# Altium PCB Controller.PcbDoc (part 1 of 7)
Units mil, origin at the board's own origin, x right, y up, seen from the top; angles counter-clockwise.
Board outline 9000 x 8000 mil, 6 copper layers (Top Layer, Layer 1, Layer 2, Layer 3, Layer 4, Bottom Layer), stack 61.699 mil thick; 761 components, 454 nets, 2369 pads, 1133 vias.
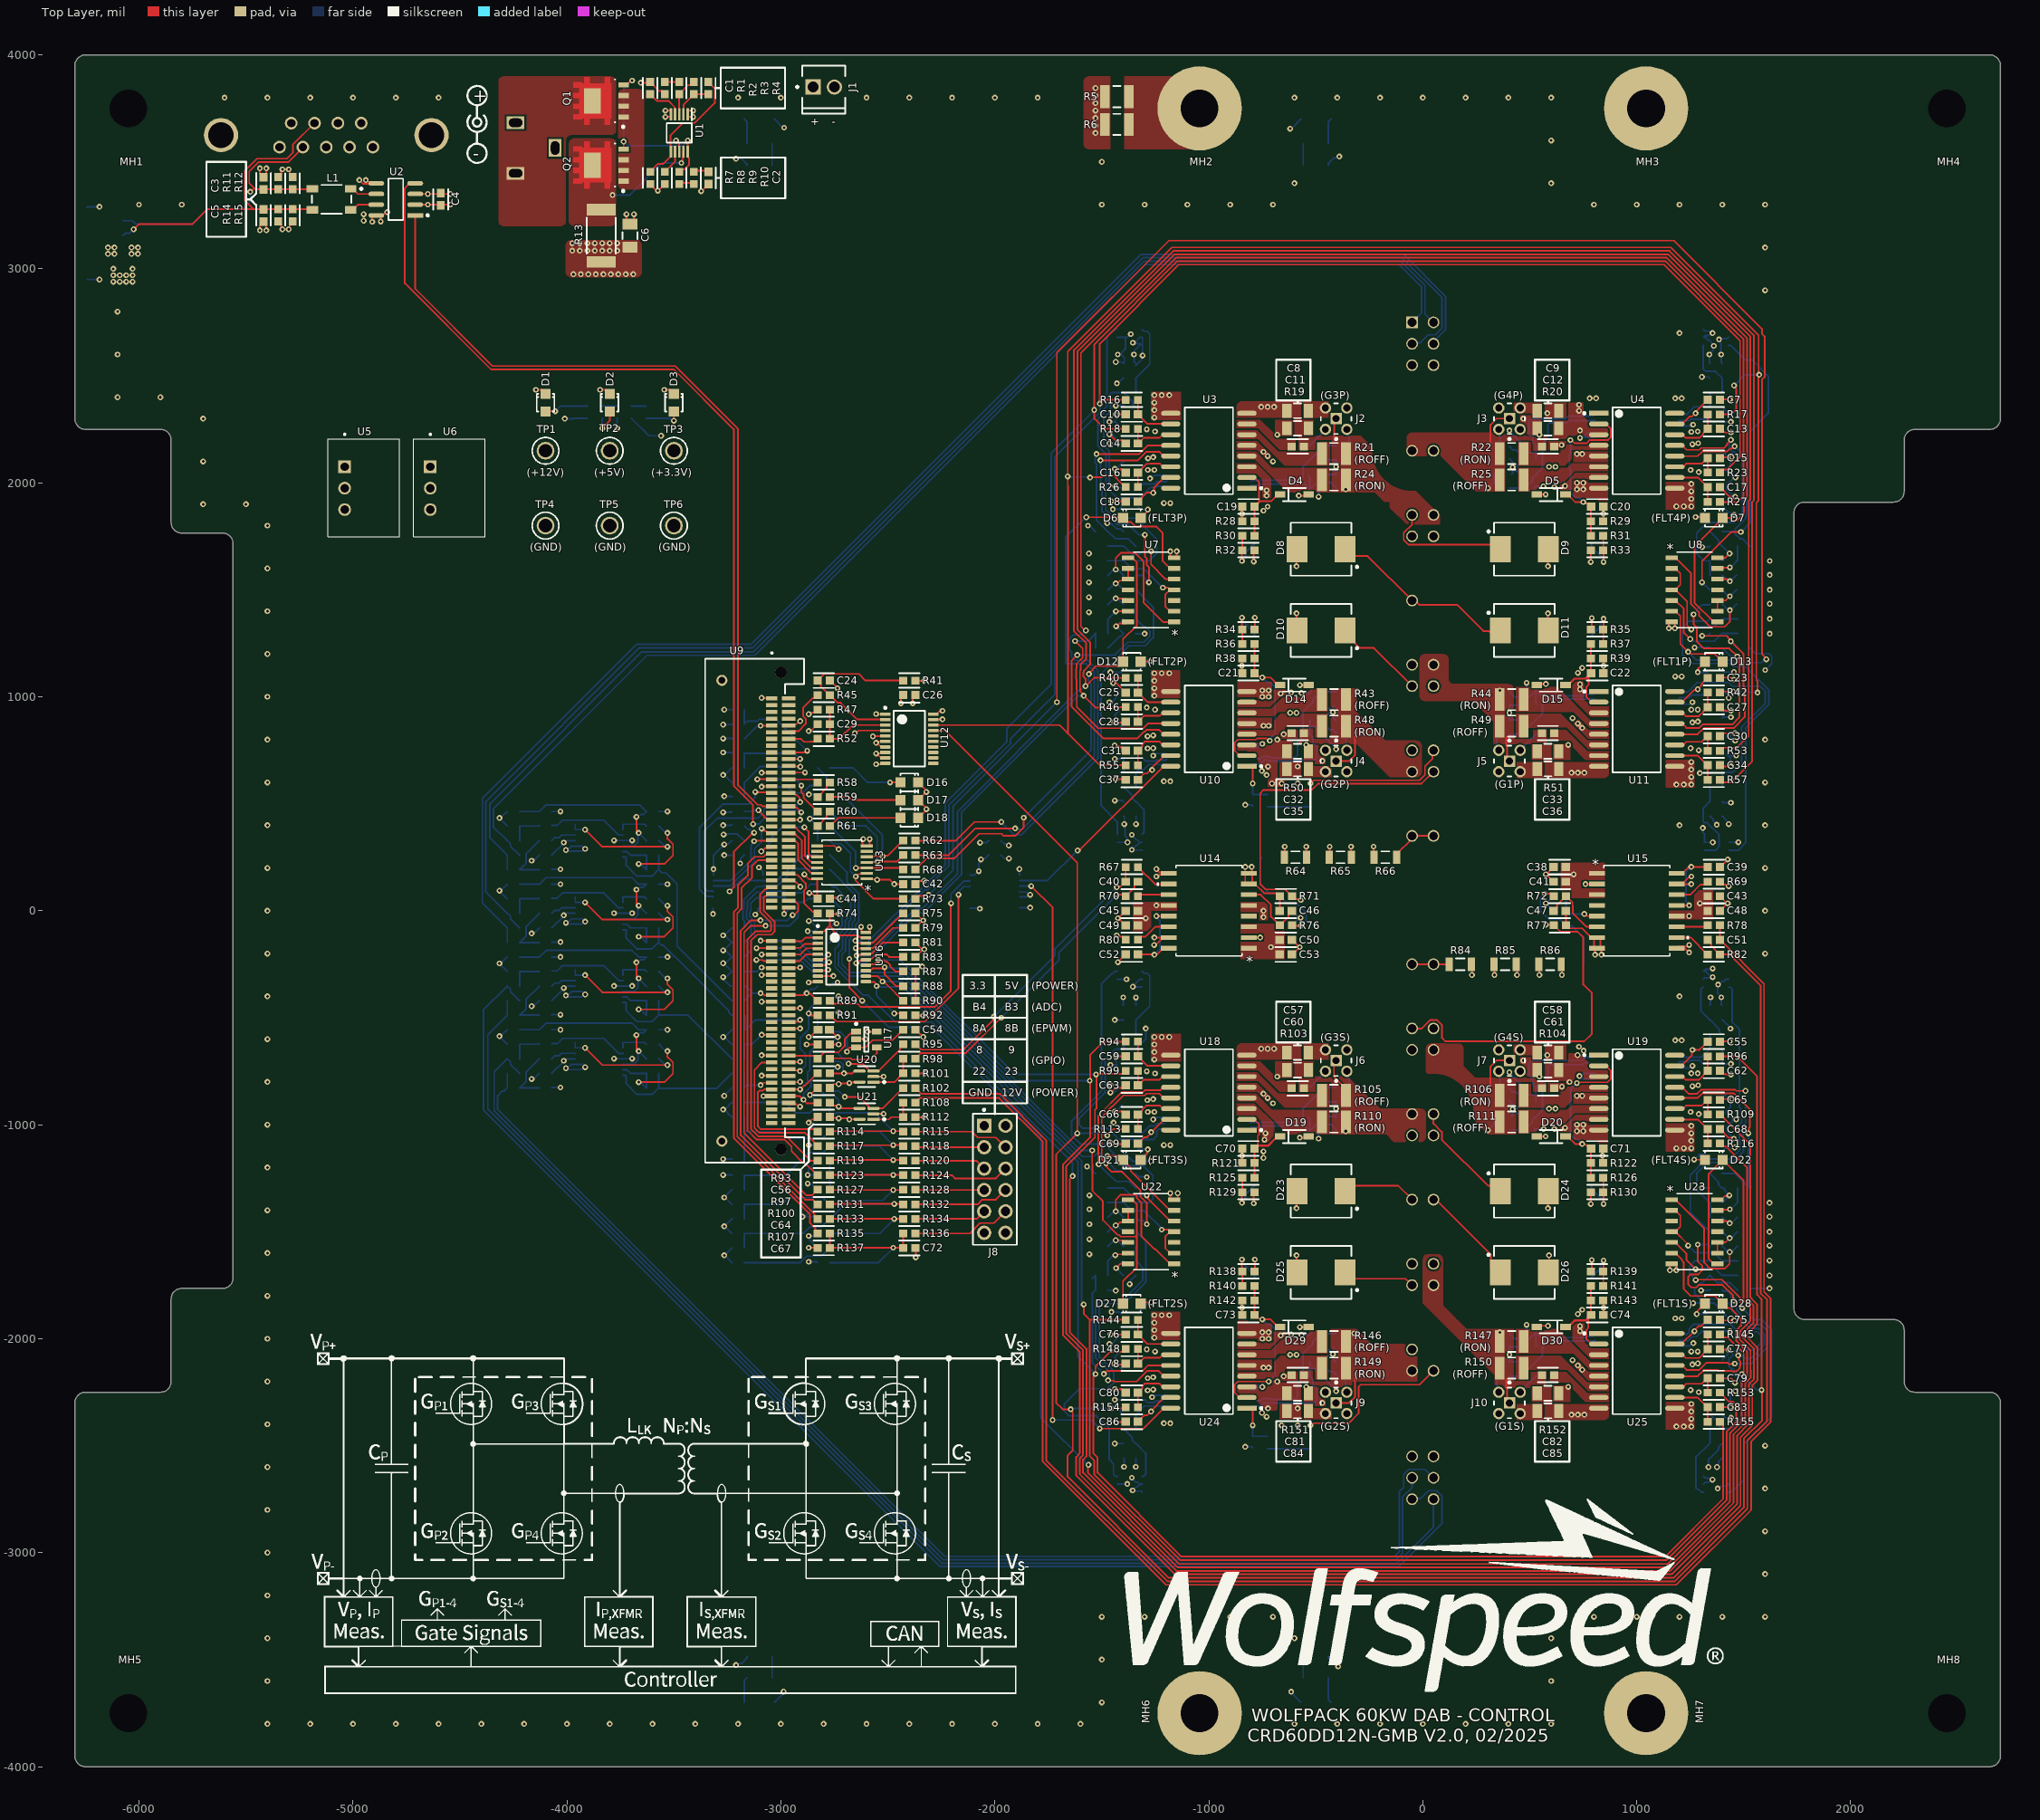
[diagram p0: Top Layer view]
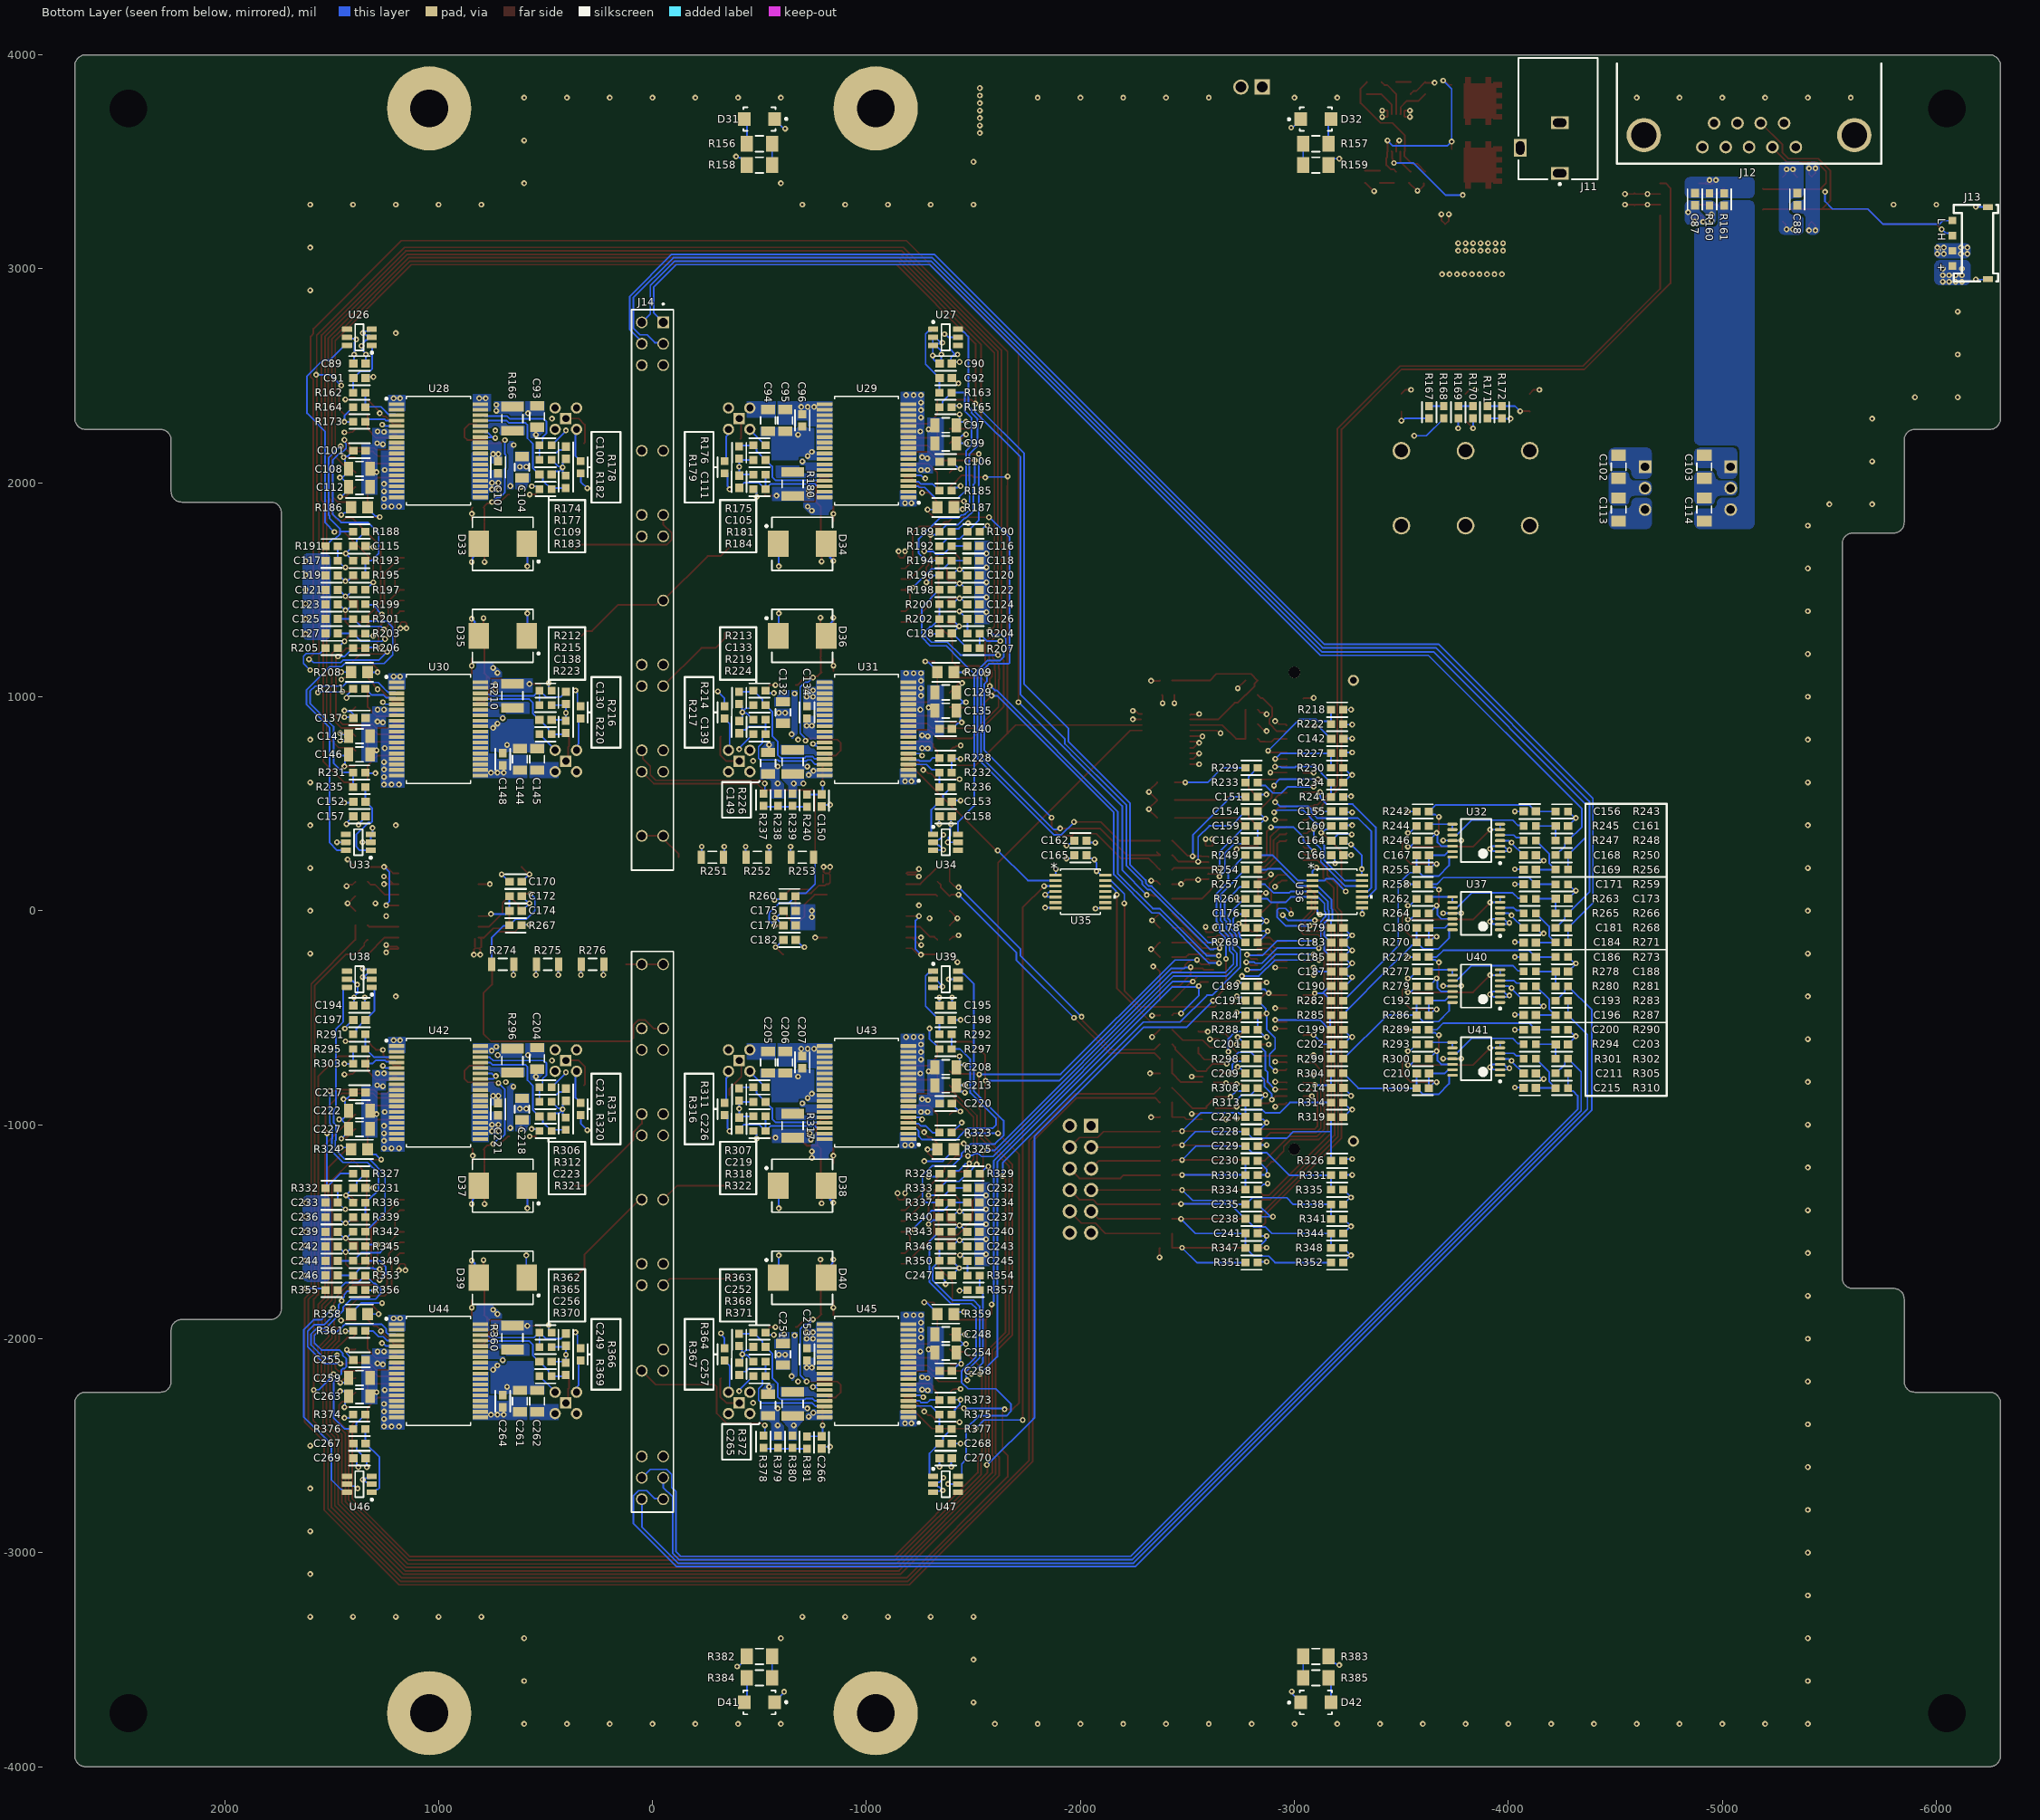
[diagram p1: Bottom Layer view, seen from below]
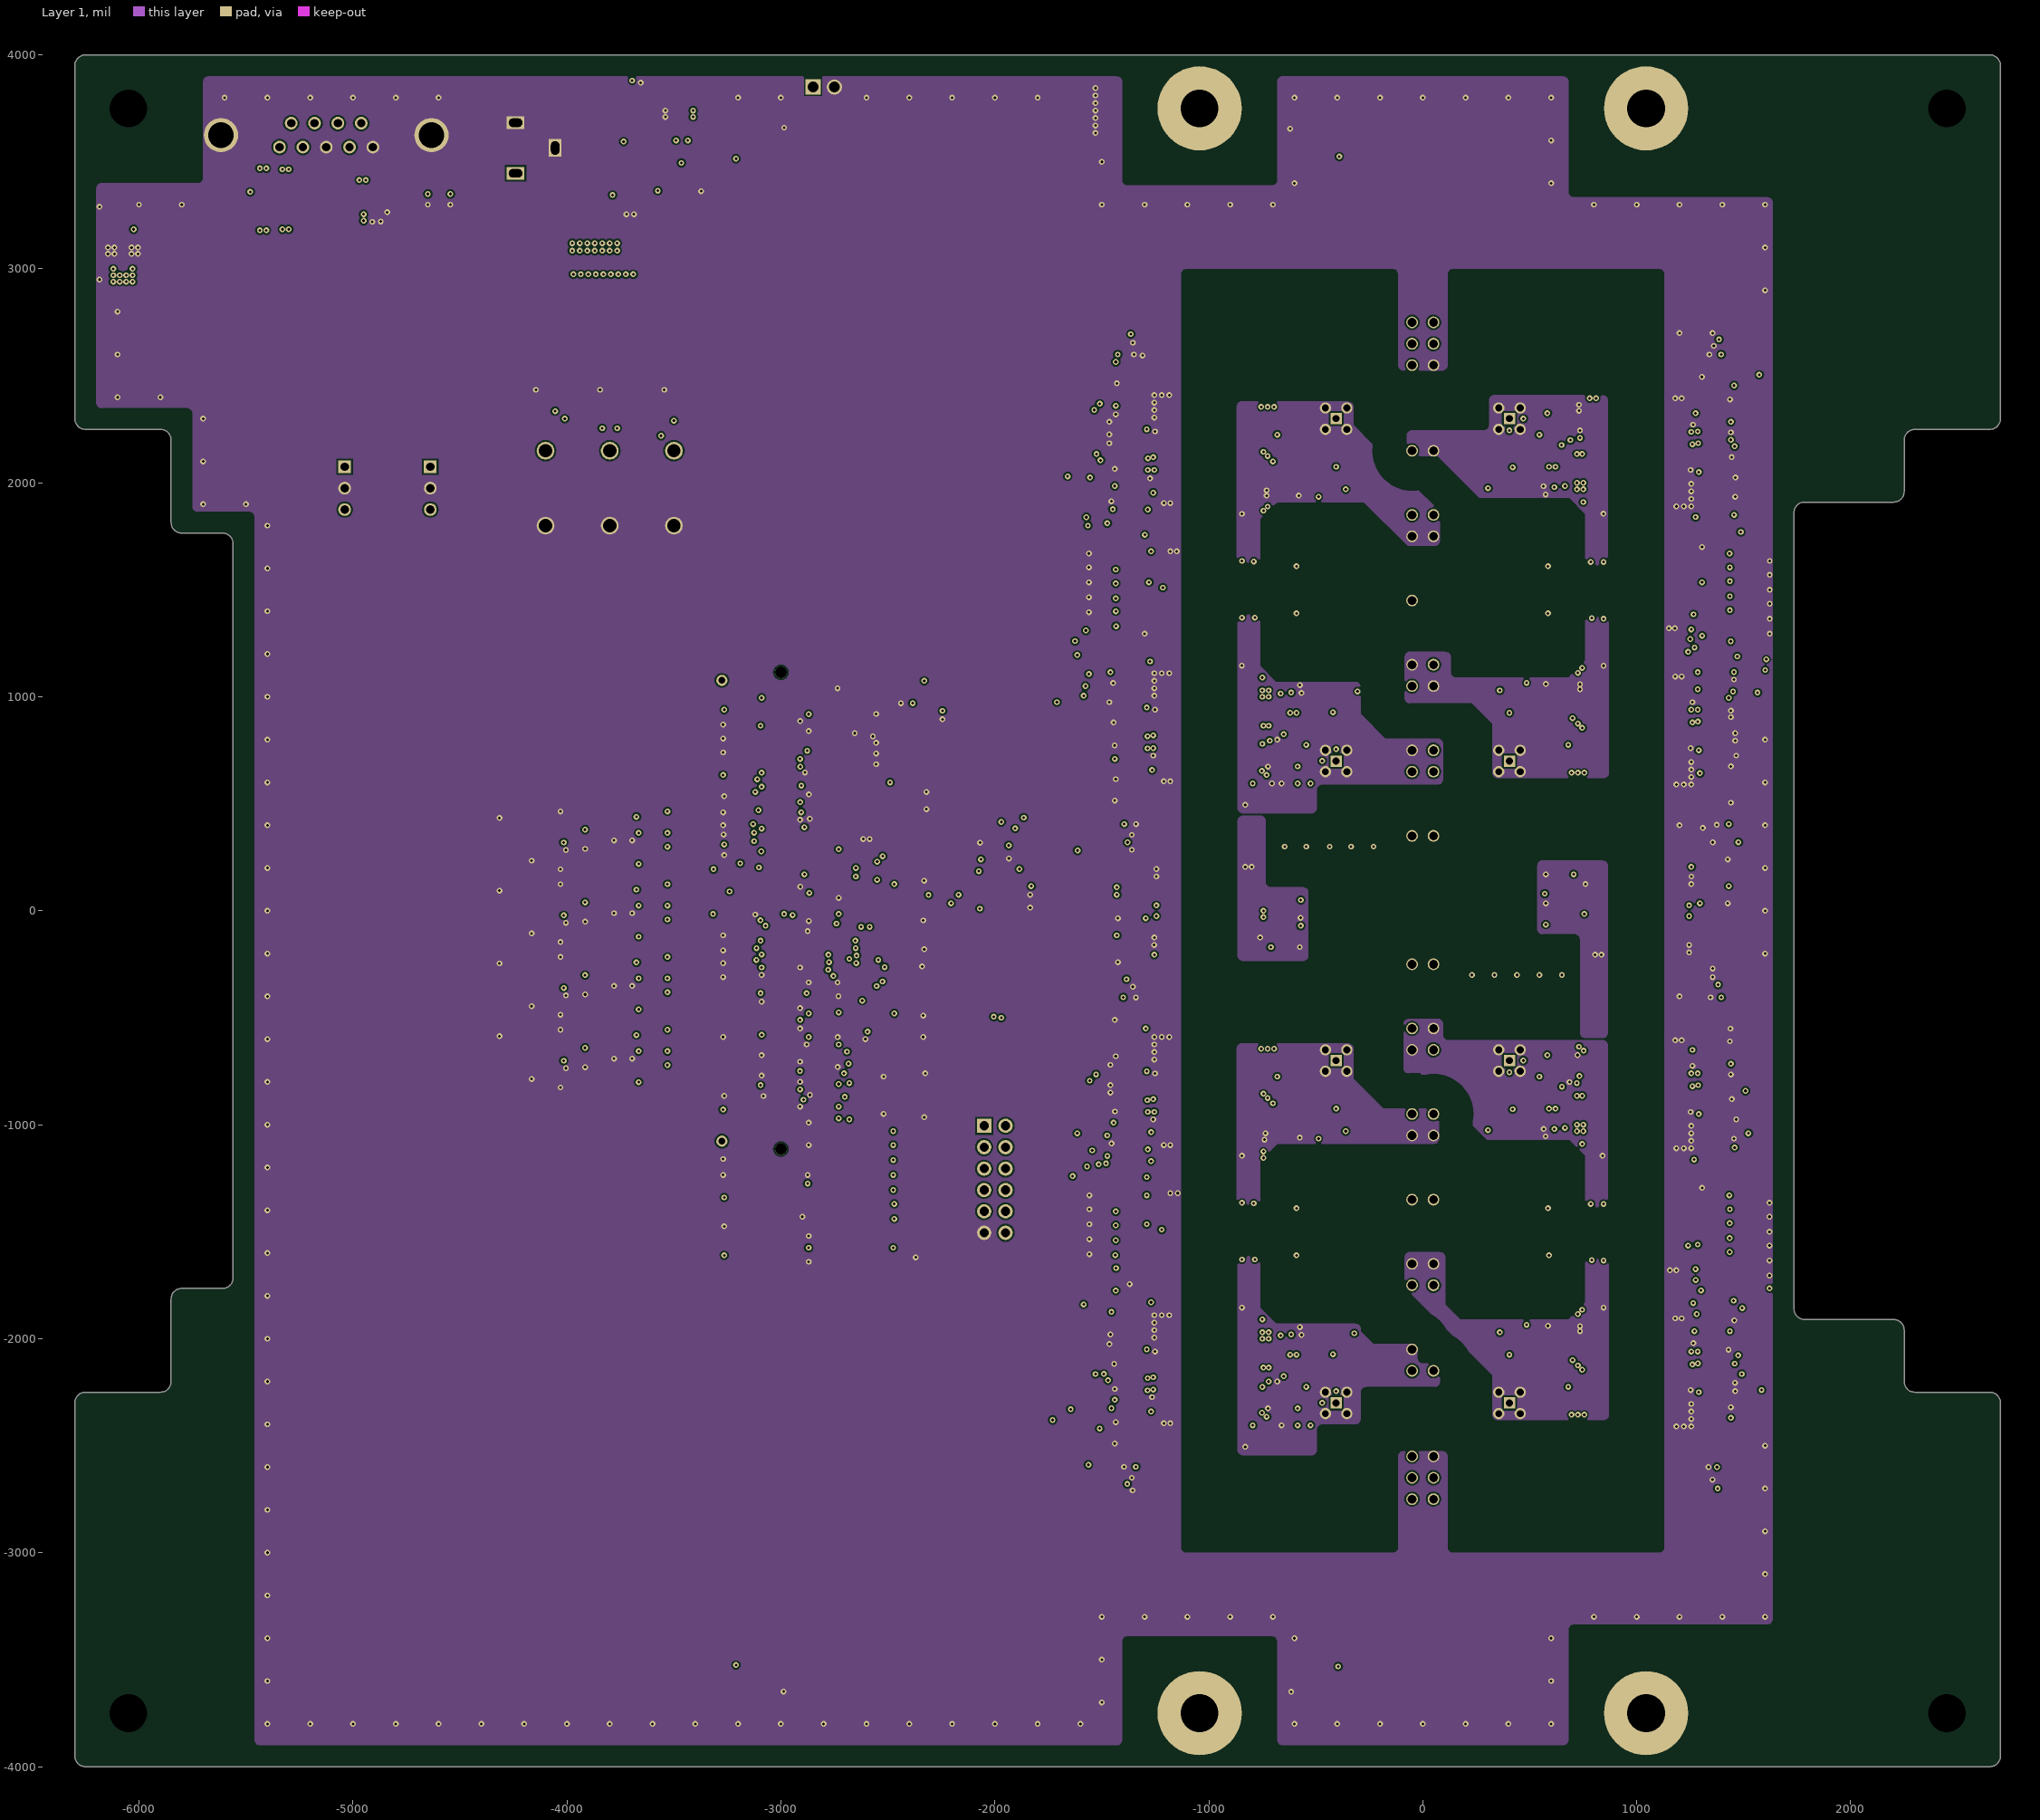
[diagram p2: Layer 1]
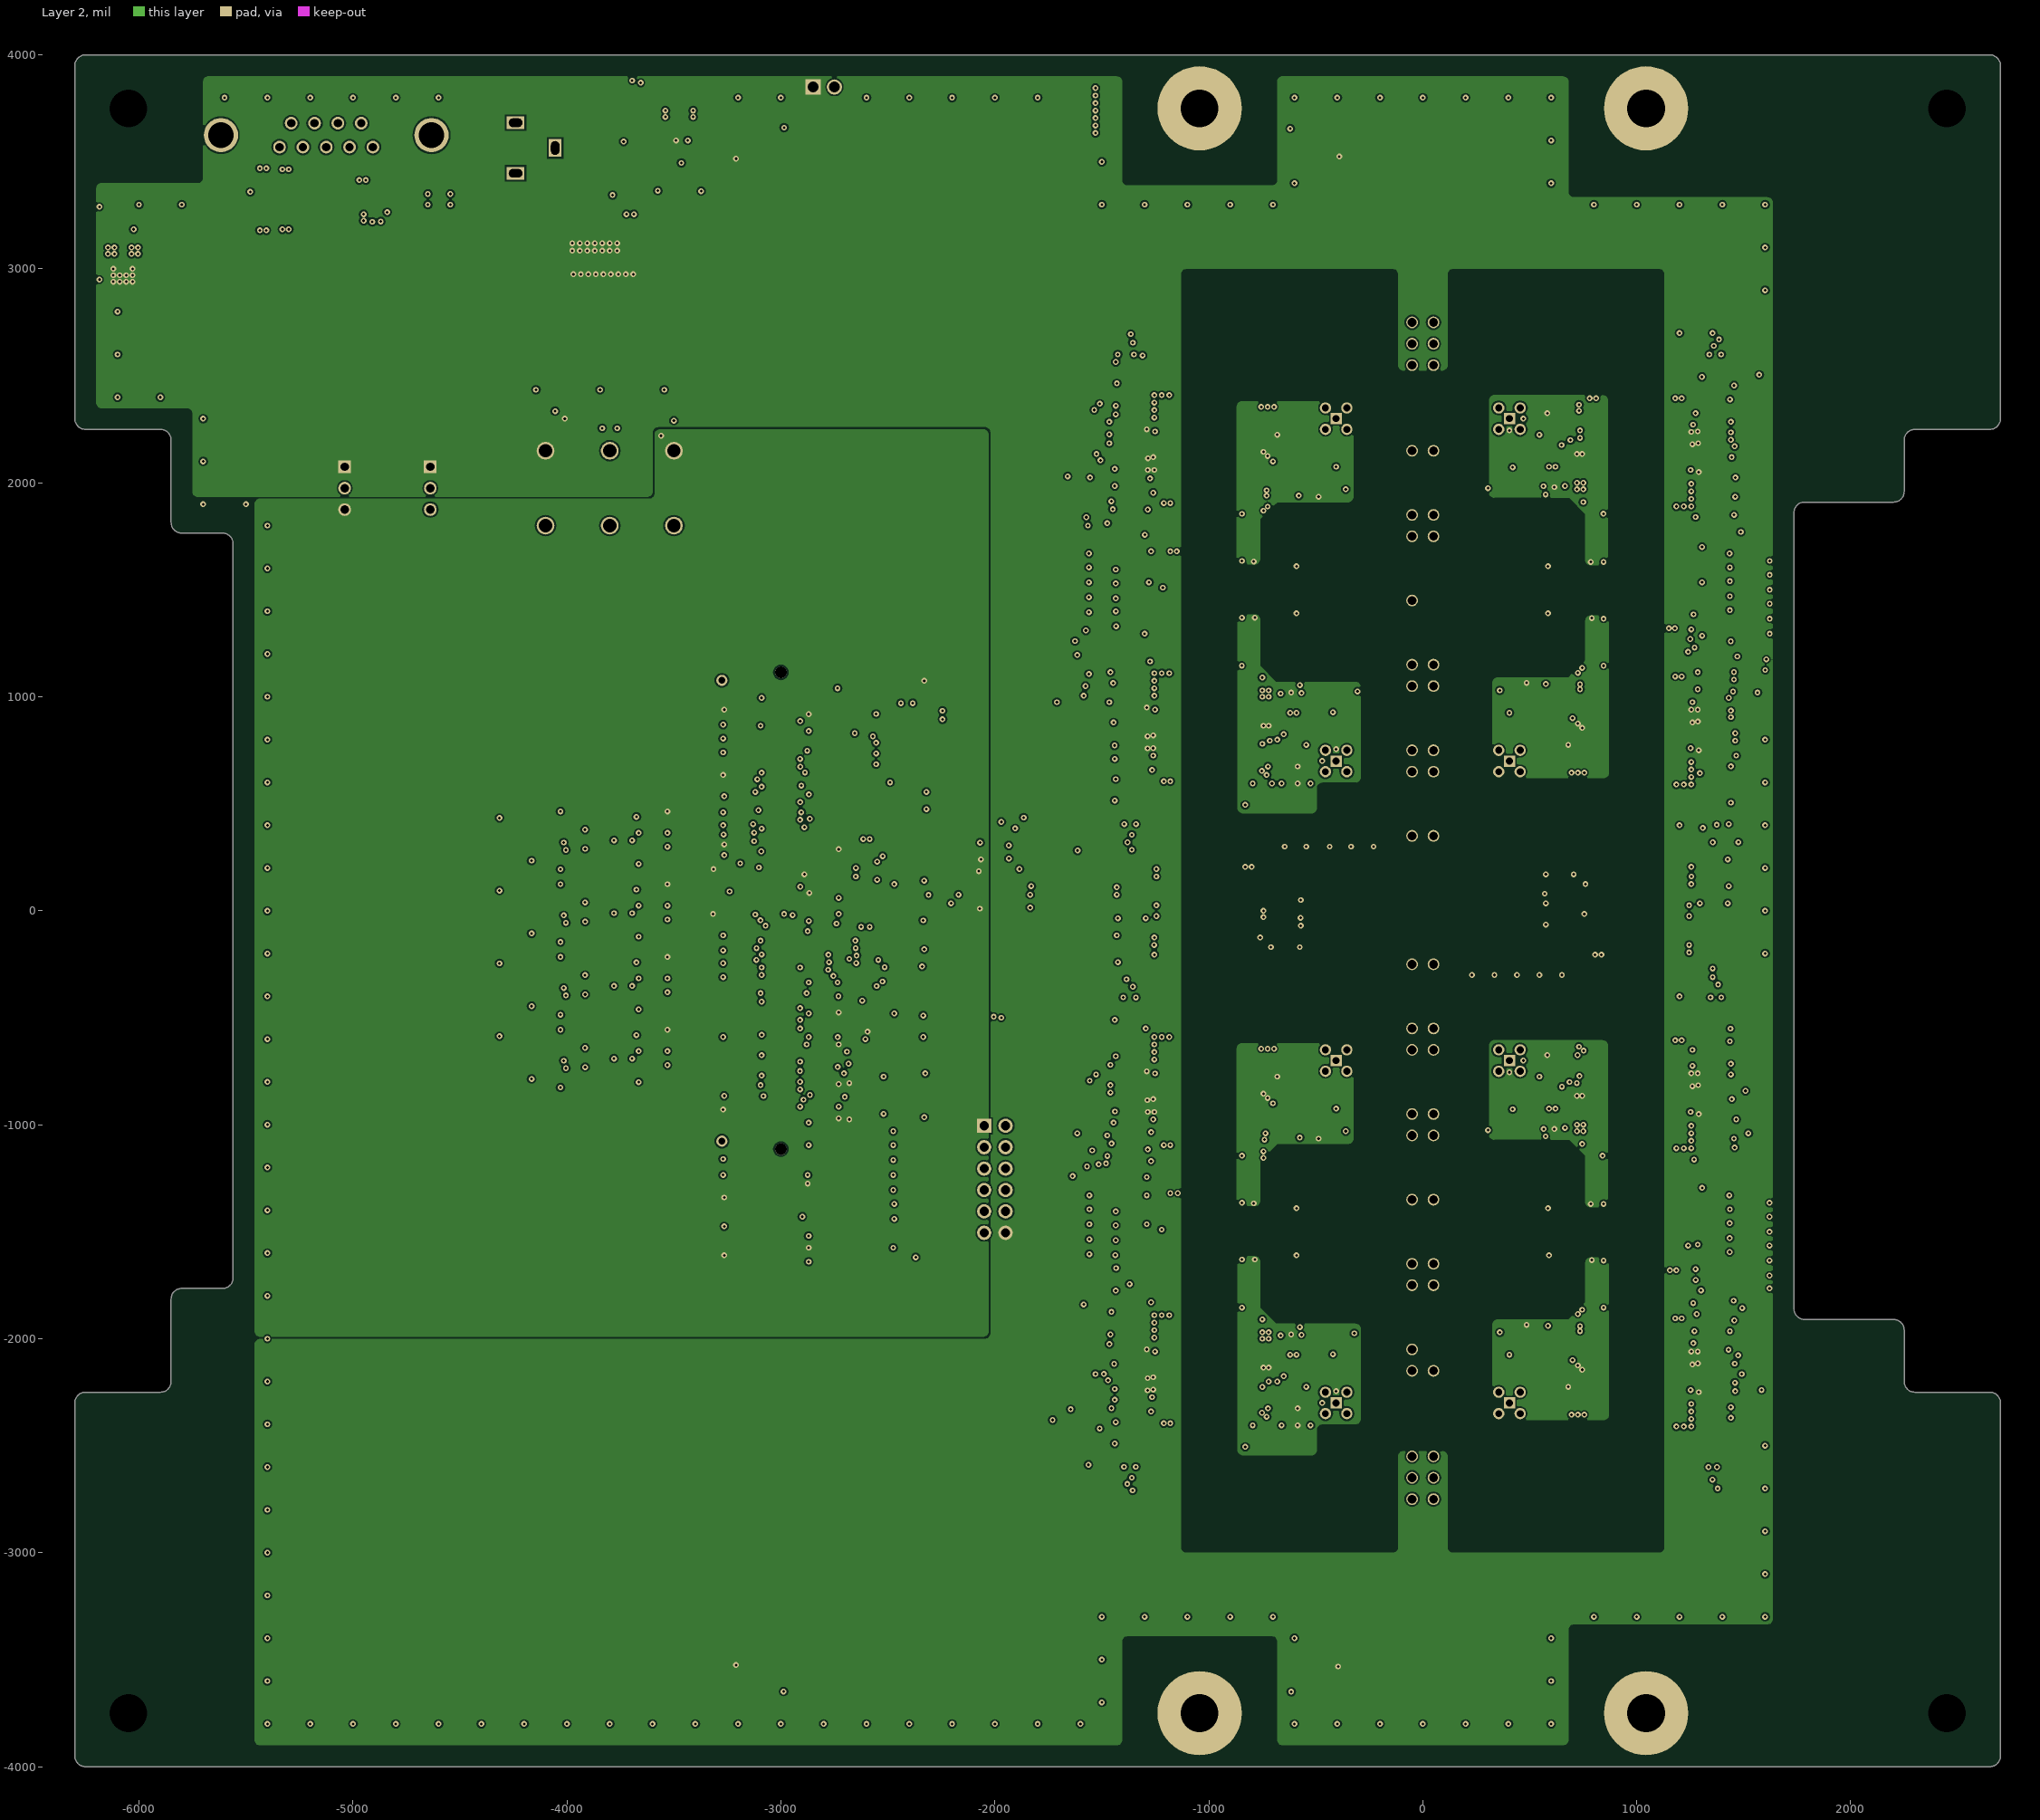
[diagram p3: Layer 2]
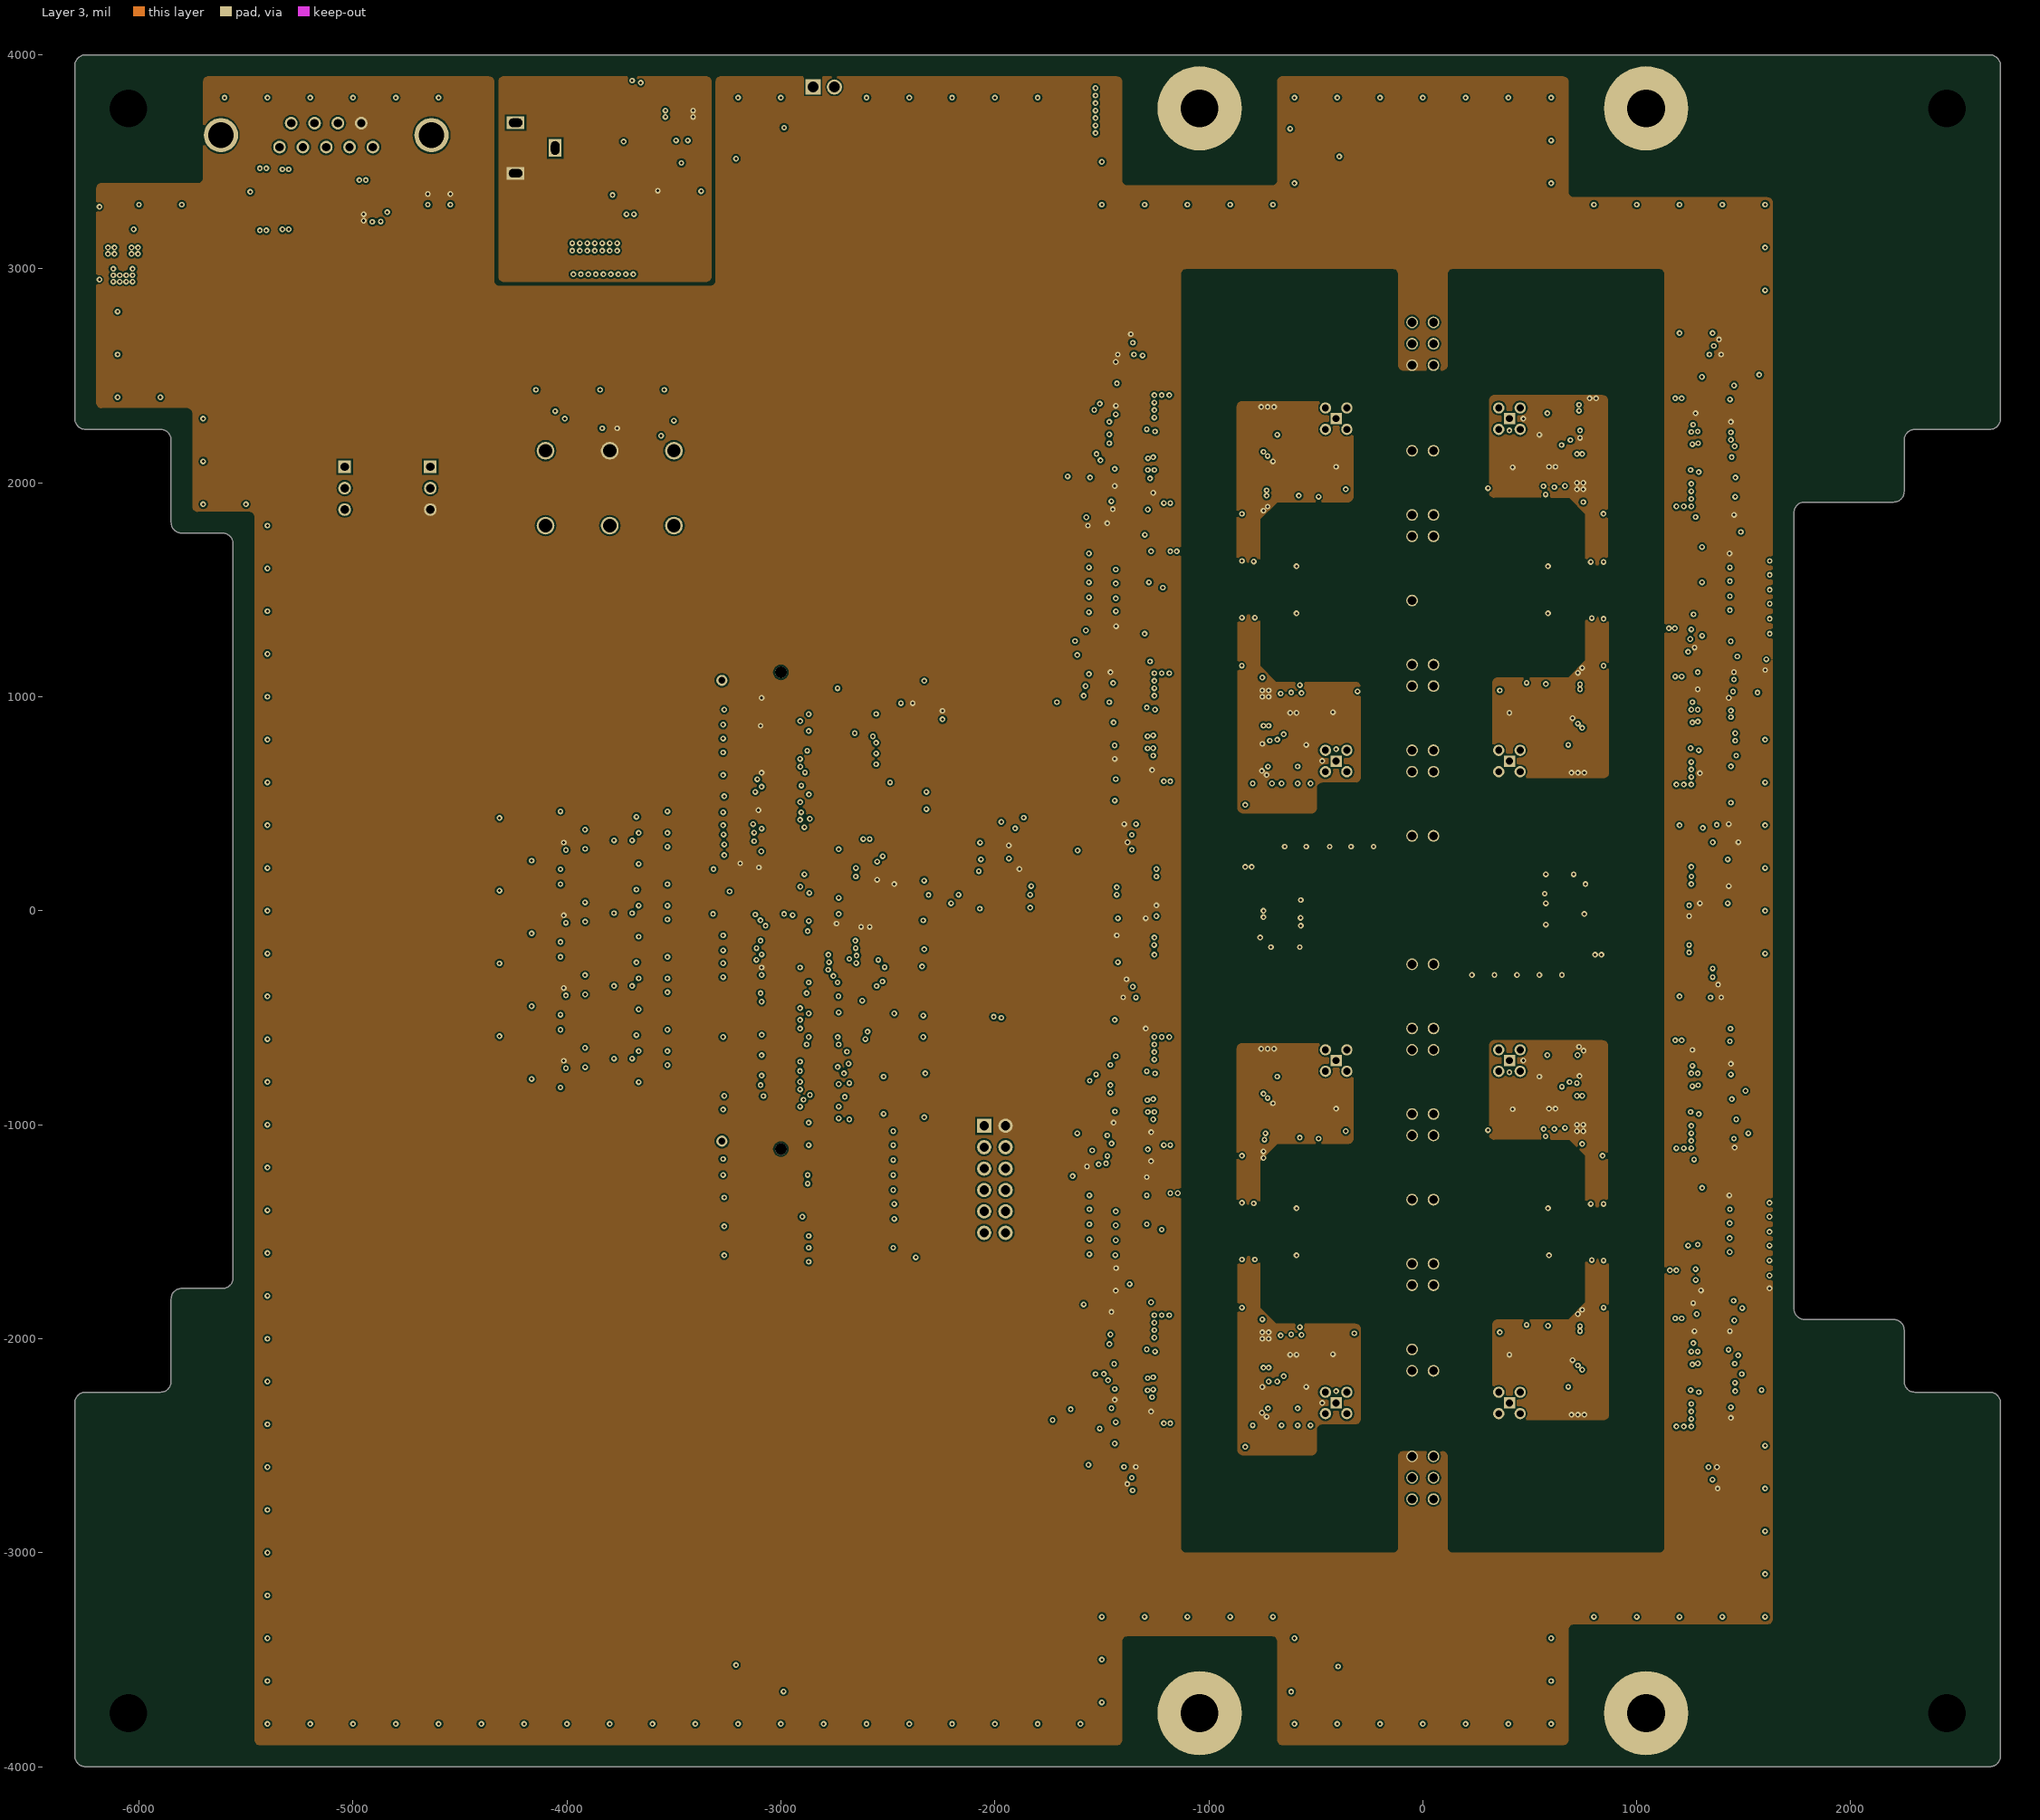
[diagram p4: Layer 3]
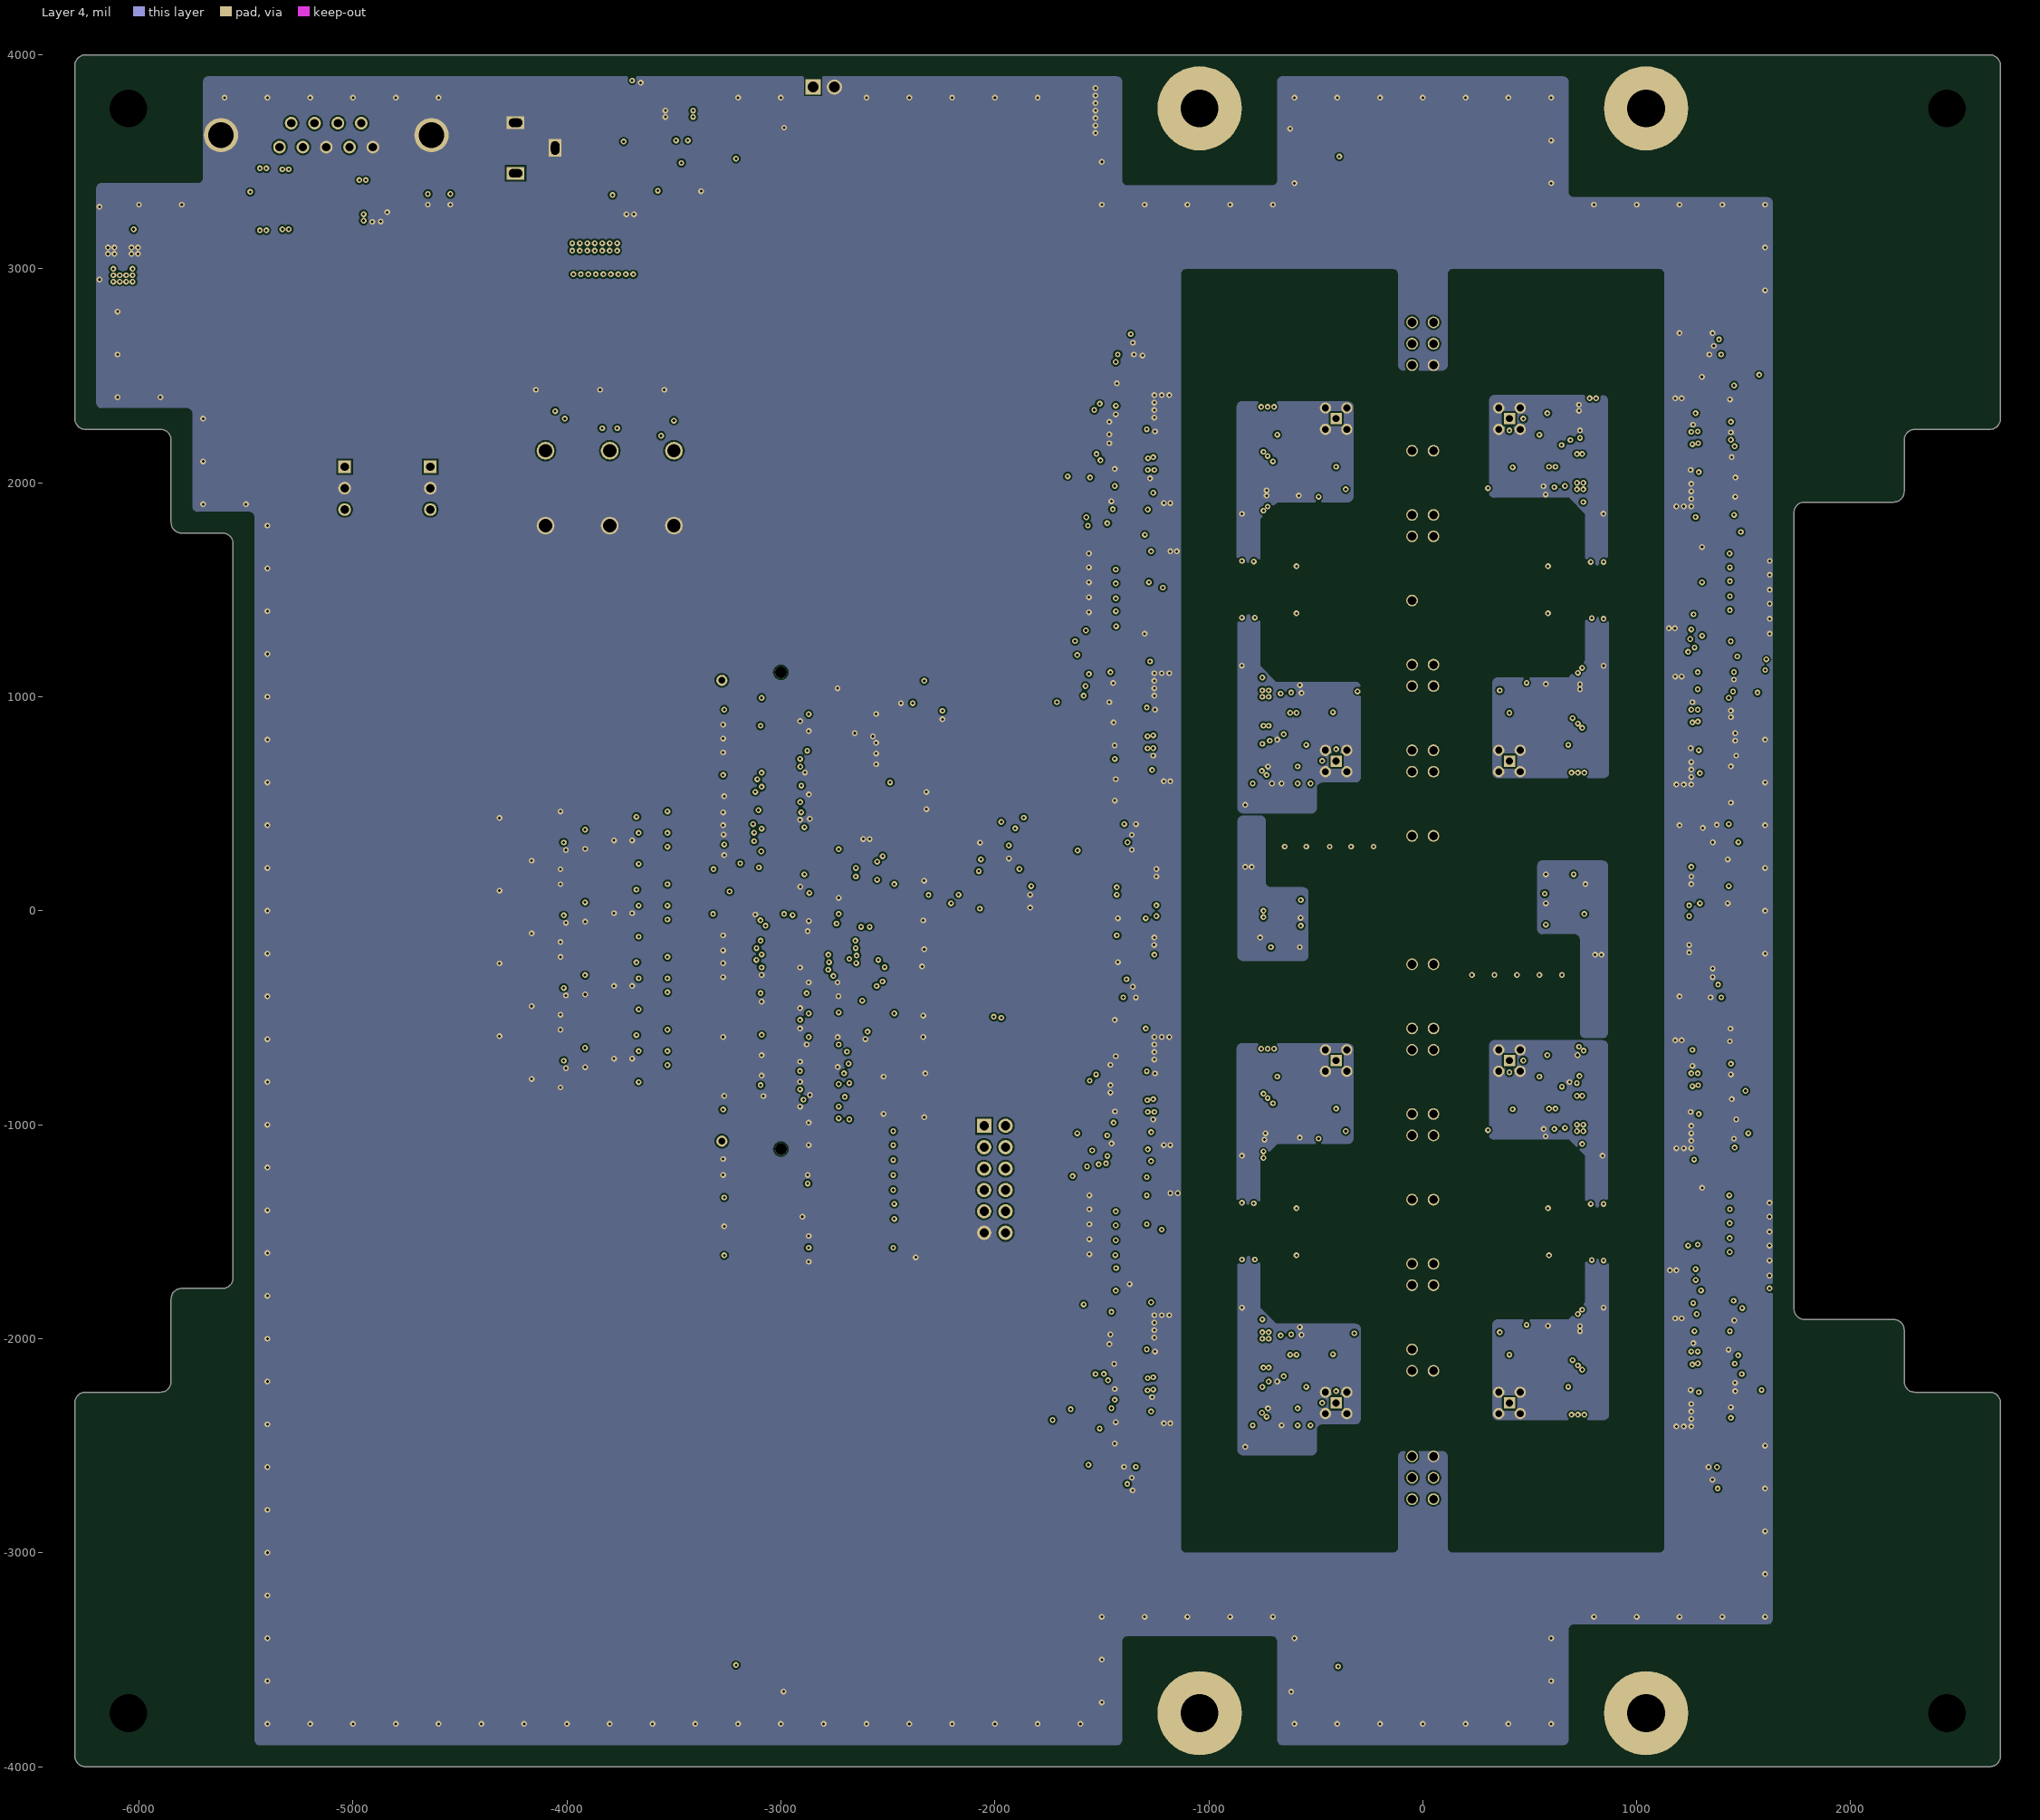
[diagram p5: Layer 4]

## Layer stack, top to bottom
Top Solder: solder mask 0.4, Solder Resist, Dk 3.5
Top Layer: signal copper 1.4
Dielectric 2: prepreg 7.7165, PP-006, Dk 4.1
Layer 1: signal copper 1.378
Dielectric 4: prepreg 16.9291, PP-006, Dk 4.1
Layer 2: signal copper 1.378
Dielectric 1: dielectric 4.096, FR-4, Dk 4.8
Layer 3: signal copper 1.378
Dielectric 5: prepreg 16.9291, PP-006, Dk 4.1
Layer 4: signal copper 1.378
Dielectric 3: prepreg 7.7165, PP-006, Dk 4.1
Bottom Layer: signal copper 1.4
Bottom Solder: solder mask 0.4, Solder Resist, Dk 3.5

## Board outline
-6300,-3950 -6300,-2300 cw(c-6250,-2300) -6250,-2250 -5900,-2250 ccw(c-5900,-2200) -5850,-2200 -5850,-1815 cw(c-5800,-1815) -5800,-1765 -5610,-1765 ccw(c-5610,-1715) -5560,-1715 -5560,1715 ccw(c-5610,1715) -5610,1765 -5800,1765 cw(c-5800,1815) -5850,1815 -5850,2200 ccw(c-5900,2200) -5900,2250 -6250,2250 cw(c-6250,2300) -6300,2300 -6300,3950 cw(c-6250,3950) -6250,4000 2650,4000 cw(c2650,3950) 2700,3950 2700,2300 cw(c2650,2300) 2650,2250 2300,2250 ccw(c2300,2200) 2250,2200 2250,1960 cw(c2200,1960) 2200,1910 1785,1910 ccw(c1785,1860) 1735,1860 1735,-1860 ccw(c1785,-1860) 1785,-1910 2200,-1910 cw(c2200,-1960) 2250,-1960 2250,-2200 ccw(c2300,-2200) 2300,-2250 2650,-2250 cw(c2650,-2300) 2700,-2300 2700,-3950 cw(c2650,-3950) 2650,-4000 -6250,-4000 cw(c-6250,-3950)

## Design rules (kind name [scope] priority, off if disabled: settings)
Clearance "Mounting Hole" [HoleDiameter = 177.165] p1: gap=160 ignorepadtopadclearanceinfootprint=TRUE
Clearance P-_CLASS [InNetClass('P-_CLASS') vs Not (InNetClass('P-_CLASS') Or InNetClass('2PMID_CLASS') Or InNetClass('4PMID_CLASS') Or InNetClass('PMID_CLASS'))] p2: gap=160 ignorepadtopadclearanceinfootprint=FALSE except(8: Arc-Hole Track-Hole SMDPad-Hole THPad-Hole Via-Hole Fill-Hole Poly-Hole Region-Hole Text-Hole)
Clearance S-_CLASS [InNetClass('S-_CLASS') vs Not (InNetClass('S-_CLASS') Or InNetClass('2SMID_CLASS') Or InNetClass('4SMID_CLASS') Or InNetClass('SMID_CLASS'))] p3: gap=160 ignorepadtopadclearanceinfootprint=FALSE except(8: Arc-Hole Track-Hole SMDPad-Hole THPad-Hole Via-Hole Fill-Hole Poly-Hole Region-Hole Text-Hole)
Clearance 1P_CLASS [InNetClass('1P_CLASS') vs Not (InNetClass('1P_CLASS') Or InNetClass('1PMID_CLASS') Or InNetClass('2PMID_CLASS'))] p4: gap=160 ignorepadtopadclearanceinfootprint=FALSE except(8: Arc-Hole Track-Hole SMDPad-Hole THPad-Hole Via-Hole Fill-Hole Poly-Hole Region-Hole Text-Hole)
Clearance 1S_CLASS [InNetClass('1S_CLASS') vs Not (InNetClass('1S_CLASS') Or InNetClass('1SMID_CLASS') Or InNetClass('2SMID_CLASS'))] p5: gap=160 ignorepadtopadclearanceinfootprint=FALSE except(8: Arc-Hole Track-Hole SMDPad-Hole THPad-Hole Via-Hole Fill-Hole Poly-Hole Region-Hole Text-Hole)
Clearance 3P_CLASS [InNetClass('3P_CLASS') vs Not (InNetClass('3P_CLASS') Or InNetClass('3PMID_CLASS') Or InNetClass('4PMID_CLASS'))] p6: gap=160 ignorepadtopadclearanceinfootprint=FALSE except(8: Arc-Hole Track-Hole SMDPad-Hole THPad-Hole Via-Hole Fill-Hole Poly-Hole Region-Hole Text-Hole)
Clearance 3S_CLASS [InNetClass('3S_CLASS') vs Not (InNetClass('3S_CLASS') Or InNetClass('3SMID_CLASS') Or InNetClass('4SMID_CLASS'))] p7: gap=160 ignorepadtopadclearanceinfootprint=FALSE except(8: Arc-Hole Track-Hole SMDPad-Hole THPad-Hole Via-Hole Fill-Hole Poly-Hole Region-Hole Text-Hole)
Clearance 1PMID_CLASS [InNetClass('1PMID_CLASS') vs InNetClass('1P_CLASS') Or InNetClass('P+_CLASS')] p8: gap=80 ignorepadtopadclearanceinfootprint=FALSE
Clearance 2PMID_CLASS [InNetClass('2PMID_CLASS') vs InNetClass('2P_CLASS') Or InNetClass('1P_CLASS')] p9: gap=80 ignorepadtopadclearanceinfootprint=FALSE
Clearance 3PMID_CLASS [InNetClass('2PMID_CLASS') vs InNetClass('3P_CLASS') Or InNetClass('P+_CLASS')] p10: gap=80 ignorepadtopadclearanceinfootprint=FALSE
Clearance 4PMID_CLASS [InNetClass('4PMID_CLASS') vs InNetClass('4P_CLASS') Or InNetClass('3P_CLASS')] p11: gap=80 ignorepadtopadclearanceinfootprint=FALSE
Clearance Default [All] p12: gap=8 ignorepadtopadclearanceinfootprint=TRUE
HoleSize [All] p1: absolutevalues=TRUE maxlimit=200 minlimit=1 maxpercent=80.000 minpercent=20.000
MinimumSolderMaskSliver [All] p1: minsoldermaskwidth=1.8
PolygonConnect [All] p1: connectstyle=Direct reliefconductorwidth=10 reliefentries=4 polygonreliefangle="90 Angle" airgapwidth=10
RoutingVias [All] p1: holewidth=28 width=50 viastyle="Through Hole" minholewidth=28 minwidth=50 maxholewidth=28 maxwidth=50
SilkToSilkClearance [All] p1: silktosilkclearance=6
SilkToSolderMaskClearance [IsPad] p1: minsilkscreentomaskgap=6 clearancetoexposedcopper=TRUE
SolderMaskExpansion [All] p1: expansion=4 istentingtop=FALSE
SupplyNets "Schematic Supply Nets_9" [InNet('+3.3V')] p1: voltage=0.000
SupplyNets "Schematic Supply Nets_7" [InNet('GND')] p2: voltage=0.000
SupplyNets "Schematic Supply Nets_5" [InNet('VIN')] p3: voltage=0.000
SupplyNets "Schematic Supply Nets_4" [InNet('GND_P')] p4: voltage=0.000
SupplyNets "Schematic Supply Nets_3" [InNet('GND_S')] p5: voltage=0.000
SupplyNets "Schematic Supply Nets_2" [InNet('+12V')] p6: voltage=0.000
SupplyNets "Schematic Supply Nets" [InNet('+5V')] p7: voltage=0.000
Width [All] p1: maxlimit=50 minlimit=8 preferedwidth=8
26 further rules are at their usual default settings.

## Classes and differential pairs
component class "Fault Logic - P": C89 C90 C91 C92 C115 C116 C117 C118 C119 C120 C121 C122 C123 C124 C125 C126 C127 C128 C151 C152 C153 C154 C157 C158 C159 C163 D6 D7 D12 D13 R62 R63 R68 R73 R162 R163 R164 R165 R186 R187 R188 R189 R190 R191 R192 R193 R194 R195 R196 R197 R198 R199 R200 R201 R202 R203 R204 R205 R206 R207 R208 R209 R231 R232 R235 R236 U7 U8 U26 U27 U33 U34
component class "Drivers - 34S": C55 C57 C58 C59 C60 C61 C62 C63 C65 C66 C68 C69 C70 C71 C204 C205 C206 C207 C208 C213 C216 C217 C218 C219 C220 C221 C222 C223 C226 C227 D19 D20 D23 D24 D37 D38 J6 J7 R94 R96 R99 R103 R104 R105 R106 R109 R110 R111 R113 R116 R121 R122 R125 R126 R129 R130 R296 R303 R306 R307 R311 R312 R315 R316 R317 R318 R320 R321 R322 R323 U18 U19 U42 U43
component class "Current Sense - P": C156 C161 C167 C168 C169 C171 C173 C180 C181 C184 C190 C199 R242 R243 R244 R245 R246 R247 R248 R250 R255 R256 R258 R259 R262 R263 R264 R265 R266 R268 R270 R271 R282 R285 U32 U37
component class "Fault Logic - S": C160 C179 C183 C185 C194 C195 C197 C198 C231 C232 C233 C234 C236 C237 C239 C240 C242 C243 C244 C245 C246 C247 C267 C268 C269 C270 D21 D22 D27 D28 R249 R254 R257 R261 R291 R292 R295 R297 R324 R325 R327 R328 R329 R332 R333 R336 R337 R339 R340 R342 R343 R345 R346 R349 R350 R353 R354 R355 R356 R357 R358 R359 R374 R375 R376 R377 U22 U23 U38 U39 U46 U47
component class "Current Sense - S": C186 C188 C192 C193 C196 C200 C202 C203 C210 C211 C214 C215 R272 R273 R277 R278 R279 R280 R281 R283 R286 R287 R289 R290 R293 R294 R299 R300 R301 R302 R304 R305 R309 R310 U40 U41
component class "Level Shifting": C24 C26 C29 C42 C44 C162 C164 C165 C166 C176 C178 C189 C191 R41 R45 R47 R52 R74 R75 R79 R81 R83 R87 R88 R89 R90 R91 R92 R269 U12 U13 U16 U35 U36
net class SMID_CLASS: NetR84_1 NetR85_1 NetR85_2 NetR86_1 NetR86_2
net class PMID_CLASS: NetR64_1 NetR64_2 NetR65_1 NetR65_2 NetR66_1
component class "Drivers - 12S": C73 C74 C75 C76 C77 C78 C79 C80 C81 C82 C83 C84 C85 C86 C248 C249 C251 C252 C253 C254 C255 C256 C257 C258 C259 C261 C262 C263 C264 C265 C266 D25 D26 D29 D30 D39 D40 J9 J10 R138 R139 R140 R141 R142 R143 R144 R145 R146 R147 R148 R149 R150 R151 R152 R153 R154 R155 R360 R361 R362 R363 R364 R365 R366 R367 R368 R369 R370 R371 R372 R373 R378 R379 R380 R381 U24 U25 U44 U45
net class 2SMID_CLASS: D_MID_2S
net class S-_CLASS: +15V_2S +15V_4S -4V_2S -4V_4S AIN_2S AIN_4S_NOTUSED CLMP_2S CLMP_4S D_BIAS_2S D_BIAS_4S DCDCO_S FBVDD_2S FBVDD_4S FBVEE_2S FBVEE_4S G_2S G_4S GH_2S GH_4S GL_2S GL_4S GND_S HLDOO_N INP_S NCS_NOTUSED NetR72_1 NTC_S NTC_S_BIAS OC_2S OC_4S RLIM_2S RLIM_4S S- S_2S S_4S
net class 1SMID_CLASS: D_MID_1S
net class 1S_CLASS: +15V_1S -4V_1S AIN_1S_NOTUSED CLMP_1S D_2S D_BIAS_1S FBVDD_1S FBVEE_1S G_1S GH_1S GL_1S OC_1S RLIM_1S S_1S
component class Controller: C1 C2 C6 C72 C102 C103 C113 C114 C142 C155 C187 C224 C228 C229 C230 C235 C238 C241 D1 D2 D3 D16 D17 D18 D31 D32 D41 D42 J8 Q1 Q2 R1 R2 R3 R4 R7 R8 R9 R10 R13 R58 R59 R60 R61 R114 R115 R117 R118 R119 R120 R123 R124 R127 R128 R131 R132 R133 R134 R135 R136 R137 R156 R157 R158 R159 R167 R168 R169 R170 R171 R172 R218 R222 R227 R229 R230 R233 R234 R241 R313 R314 R319 R326 R330 R331 R334 R335 R338 R341 R344 R347 R348 R351 R352 R382 R383 R384 R385 U1 U5 U6 U9
net class S+_CLASS: D_1S D_3S S+
net class 3SMID_CLASS: D_MID_3S
net class 3S_CLASS: +15V_3S -4V_3S AIN_3S_NOTUSED CLMP_3S D_4S D_BIAS_3S FBVDD_3S FBVEE_3S G_3S GH_3S GL_3S OC_3S RLIM_3S S_3S
net class 4SMID_CLASS: D_MID_4S
component class "Drivers - 34P": C7 C8 C9 C10 C11 C12 C13 C14 C15 C16 C17 C18 C19 C20 C93 C94 C95 C96 C97 C99 C100 C101 C104 C105 C106 C107 C108 C109 C111 C112 D4 D5 D8 D9 D33 D34 J2 J3 R16 R17 R18 R19 R20 R21 R22 R23 R24 R25 R26 R27 R28 R29 R30 R31 R32 R33 R166 R173 R174 R175 R176 R177 R178 R179 R180 R181 R182 R183 R184 R185 U3 U4 U28 U29
net class 4PMID_CLASS: D_MID_4P
net class 3PMID_CLASS: D_MID_3P
net class 3P_CLASS: +15V_3P -4V_3P AIN_3P_NOTUSED CLMP_3P D_4P D_BIAS_3P FBVDD_3P FBVEE_3P G_3P GH_3P GL_3P OC_3P RLIM_3P S_3P
component class "Drivers - 12P": C21 C22 C23 C25 C27 C28 C30 C31 C32 C33 C34 C35 C36 C37 C129 C130 C132 C133 C134 C135 C137 C138 C139 C140 C141 C144 C145 C146 C148 C149 C150 D10 D11 D14 D15 D35 D36 J4 J5 R34 R35 R36 R37 R38 R39 R40 R42 R43 R44 R46 R48 R49 R50 R51 R53 R55 R57 R210 R211 R212 R213 R214 R215 R216 R217 R219 R220 R223 R224 R226 R228 R237 R238 R239 R240 U10 U11 U30 U31
net class P+_CLASS: D_13P P+
net class 2PMID_CLASS: D_MID_2P
net class P-_CLASS: +15V_2P +15V_4P -4V_2P -4V_4P AIN_2P AIN_4P_NOTUSED CLMP_2P CLMP_4P D_BIAS_2P D_BIAS_4P DCDCO_P FBVDD_2P FBVDD_4P FBVEE_2P FBVEE_4P G_2P G_4P GH_2P GH_4P GL_2P GL_4P GND_P HLDOO_P INP_P NCP_NOTUSED NetR76_1 NTC_P NTC_P_BIAS OC_2P OC_4P P- RLIM_2P RLIM_4P S_2P S_4P
net class 1PMID_CLASS: D_MID_1P
net class 1P_CLASS: +15V_1P -4V_1P AIN_1P_NOTUSED CLMP_1P D_2P D_BIAS_1P FBVDD_1P FBVEE_1P G_1P GH_1P GL_1P OC_1P RLIM_1P S_1P
component class "Voltage Sense": C38 C39 C40 C41 C43 C45 C46 C47 C48 C49 C50 C51 C52 C53 C64 C67 C170 C172 C174 C175 C177 C182 C201 C209 R64 R65 R66 R67 R69 R70 R71 R72 R76 R77 R78 R80 R82 R84 R85 R86 R95 R98 R100 R101 R102 R107 R108 R112 R251 R252 R253 R260 R267 R274 R275 R276 R298 R308 U14 U15 U20 U21
component class Input-Output: C3 C4 C5 C54 C56 C87 C88 J1 J11 J12 J13 J14 L1 MH1 MH2 MH3 MH4 MH5 MH6 MH7 MH8 R5 R6 R11 R12 R14 R15 R93 R97 R160 R161 R284 R288 TP1 TP2 TP3 TP4 TP5 TP6 U2 U17

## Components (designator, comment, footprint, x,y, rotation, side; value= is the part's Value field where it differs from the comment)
C1 "CL10C560JB8NNNC" FP-C0603C-CF-IPC_B -3611,3845 r90 top value=56pF
C2 "C0603C472K3RAC7867" FP-C0603C-CF-IPC_B -3339,3425 r270 top value=4.7nF
C3 "06035A180JAT2A" FP-C0603C-CF-IPC_B -5418,3400 r90 top value=18pF
C4 "C0603C104K3RACTU" FP-C0603C-CF-IPC_B -4590,3325 r270 top value=0.10μF
C5 "06035A180JAT2A" FP-C0603C-CF-IPC_B -5418,3250 r90 top value=18pF
C6 "CL31B106KAHSFNE" FP-CL31-IPC_B -3705,3155 r90 top value=10μF
C7 "GRT188R61H225ME13D" FP-C0603C-CF-IPC_B 1360,2388 r0 top value=2.2μF
C8 "CL31B106KAHSFNE" FP-CL31-IPC_C -585,2337 r180 top value=10μF
C9 "12063C225K4T2A" FP-CL31-IPC_C 585,2337 r180 top value=2.2μF
C10 "CL10C560JB8NNNC" FP-C0603C-CF-IPC_B -1360,2320 r180 top value=56pF
C11 "CL31B106KAHSFNE" FP-CL31-IPC_C -585,2255 r0 top value=10μF
C12 "CL31B106KAHSFNE" FP-CL31-IPC_C 585,2255 r180 top value=10μF
C13 "CL10C560JB8NNNC" FP-C0603C-CF-IPC_B 1360,2252 r0 top value=56pF
C14 "CL10C560JB8NNNC" FP-C0603C-CF-IPC_B -1360,2184 r180 top value=56pF
C15 "CL10C560JB8NNNC" FP-C0603C-CF-IPC_B 1360,2116 r0 top value=56pF
C16 "CL10C560JB8NNNC" FP-C0603C-CF-IPC_B -1360,2048 r180 top value=56pF
C17 "CL10C560JB8NNNC" FP-C0603C-CF-IPC_B 1360,1980 r0 top value=56pF
C18 "GRT188R61H225ME13D" FP-C0603C-CF-IPC_B -1360,1912 r180 top value=2.2μF
C19 "CL10C560JB8NNNC" FP-C0603C-CF-IPC_B -815,1889 r180 top value=56pF
C20 "CL10C560JB8NNNC" FP-C0603C-CF-IPC_B 815,1889 r0 top value=56pF
C21 "CL10C560JB8NNNC" FP-C0603C-CF-IPC_B -815,1111 r180 top value=56pF
C22 "CL10C560JB8NNNC" FP-C0603C-CF-IPC_B 815,1111 r0 top value=56pF
C23 "GRT188R61H225ME13D" FP-C0603C-CF-IPC_B 1360,1088 r0 top value=2.2μF
C24 "CL10C560JB8NNNC" FP-C0603C-CF-IPC_B -2800,1076 r0 top value=56pF
C25 "CL10C560JB8NNNC" FP-C0603C-CF-IPC_B -1360,1020 r180 top value=56pF
C26 "GRT188R61H225ME13D" FP-C0603C-CF-IPC_B -2400,1008 r180 top value=2.2μF
C27 "CL10C560JB8NNNC" FP-C0603C-CF-IPC_B 1360,952 r0 top value=56pF
C28 "CL10C560JB8NNNC" FP-C0603C-CF-IPC_B -1360,884 r180 top value=56pF
C29 "CL10C560JB8NNNC" FP-C0603C-CF-IPC_B -2800,872 r180 top value=56pF
C30 "CL10C560JB8NNNC" FP-C0603C-CF-IPC_B 1360,816 r0 top value=56pF
C31 "CL10C560JB8NNNC" FP-C0603C-CF-IPC_B -1360,748 r180 top value=56pF
C32 "CL31B106KAHSFNE" FP-CL31-IPC_C -585,745 r0 top value=10μF
C33 "CL31B106KAHSFNE" FP-CL31-IPC_C 585,745 r180 top value=10μF
C34 "CL10C560JB8NNNC" FP-C0603C-CF-IPC_B 1360,680 r0 top value=56pF
C35 "12063C225K4T2A" FP-CL31-IPC_C -585,663 r0 top value=2.2μF
C36 "CL31B106KAHSFNE" FP-CL31-IPC_C 585,663 r0 top value=10μF
C37 "GRT188R61H225ME13D" FP-C0603C-CF-IPC_B -1360,612 r180 top value=2.2μF
C38 "GCM188R71H102KA37D" FP-C0603C-CF-IPC_B 640,204 r180 top value=1nF
C39 "CGA3E2X7R1H104K080AA" FP-C0603C-CF-IPC_B 1360,204 r0 top value=100nF
C40 "GRM188R72A103KA01D" FP-C0603C-CF-IPC_B -1360,136 r180 top value=10nF
C41 "CGA3E2X7R1H104K080AA" FP-C0603C-CF-IPC_B 640,136 r0 top value=100nF
C42 "GRT188R61H225ME13D" FP-C0603C-CF-IPC_B -2400,124 r0 top value=2.2μF
C43 "CGA3E1X7R1V105K080AC" FP-C0603C-CF-IPC_B 1360,68 r0 top value=1μF
C44 "GRT188R61H225ME13D" FP-C0603C-CF-IPC_B -2800,56 r0 top value=2.2μF
C45 "GCM188R71H102KA37D" FP-C0603C-CF-IPC_B -1360,0 r180 top value=1nF
C46 "GRM188R72A103KA01D" FP-C0603C-CF-IPC_B -640,0 r180 top value=10nF
C47 "GRM188R72A103KA01D" FP-C0603C-CF-IPC_B 640,0 r0 top value=10nF
C48 "GCM188R71H102KA37D" FP-C0603C-CF-IPC_B 1360,0 r0 top value=1nF
C49 "CGA3E1X7R1V105K080AC" FP-C0603C-CF-IPC_B -1360,-68 r180 top value=1μF
C50 "CGA3E2X7R1H104K080AA" FP-C0603C-CF-IPC_B -640,-136 r180 top value=100nF
C51 "GRM188R72A103KA01D" FP-C0603C-CF-IPC_B 1360,-136 r180 top value=10nF
C52 "CGA3E2X7R1H104K080AA" FP-C0603C-CF-IPC_B -1360,-204 r180 top value=100nF
C53 "GCM188R71H102KA37D" FP-C0603C-CF-IPC_B -640,-204 r0 top value=1nF
C54 "C0603C104K3RACTU" FP-C0603C-CF-IPC_B -2400,-556 r0 top value=0.10μF
C55 "GRT188R61H225ME13D" FP-C0603C-CF-IPC_B 1360,-612 r0 top value=2.2μF
C56 "C0603C104K3RACTU" FP-C0603C-CF-IPC_B -2800,-624 r180 top value=0.10μF
C57 "CL31B106KAHSFNE" FP-CL31-IPC_C -585,-663 r180 top value=10μF
C58 "12063C225K4T2A" FP-CL31-IPC_C 585,-663 r180 top value=2.2μF
C59 "CL10C560JB8NNNC" FP-C0603C-CF-IPC_B -1360,-680 r180 top value=56pF
C60 "CL31B106KAHSFNE" FP-CL31-IPC_C -585,-745 r0 top value=10μF
C61 "CL31B106KAHSFNE" FP-CL31-IPC_C 585,-745 r180 top value=10μF
C62 "CL10C560JB8NNNC" FP-C0603C-CF-IPC_B 1360,-748 r0 top value=56pF
C63 "CL10C560JB8NNNC" FP-C0603C-CF-IPC_B -1360,-816 r180 top value=56pF
C64 "CGA3E2X7R1H104K080AA" FP-C0603C-CF-IPC_B -2800,-828 r180 top value=100nF
C65 "CL10C560JB8NNNC" FP-C0603C-CF-IPC_B 1360,-884 r0 top value=56pF
C66 "CL10C560JB8NNNC" FP-C0603C-CF-IPC_B -1360,-952 r180 top value=56pF
C67 "CGA3E2X7R1H104K080AA" FP-C0603C-CF-IPC_B -2800,-964 r180 top value=100nF
C68 "CL10C560JB8NNNC" FP-C0603C-CF-IPC_B 1360,-1020 r0 top value=56pF
C69 "GRT188R61H225ME13D" FP-C0603C-CF-IPC_B -1360,-1088 r180 top value=2.2μF
C70 "CL10C560JB8NNNC" FP-C0603C-CF-IPC_B -815,-1111 r180 top value=56pF
C71 "CL10C560JB8NNNC" FP-C0603C-CF-IPC_B 815,-1111 r0 top value=56pF
C72 "CL10C560JB8NNNC" FP-C0603C-CF-IPC_B -2400,-1576 r0 top value=56pF
C73 "CL10C560JB8NNNC" FP-C0603C-CF-IPC_B -815,-1889 r180 top value=56pF
C74 "CL10C560JB8NNNC" FP-C0603C-CF-IPC_B 815,-1889 r0 top value=56pF
C75 "GRT188R61H225ME13D" FP-C0603C-CF-IPC_B 1360,-1912 r0 top value=2.2μF
C76 "CL10C560JB8NNNC" FP-C0603C-CF-IPC_B -1360,-1980 r180 top value=56pF
C77 "CL10C560JB8NNNC" FP-C0603C-CF-IPC_B 1360,-2048 r0 top value=56pF
C78 "CL10C560JB8NNNC" FP-C0603C-CF-IPC_B -1360,-2116 r180 top value=56pF
C79 "CL10C560JB8NNNC" FP-C0603C-CF-IPC_B 1360,-2184 r0 top value=56pF
C80 "CL10C560JB8NNNC" FP-C0603C-CF-IPC_B -1360,-2252 r180 top value=56pF
C81 "CL31B106KAHSFNE" FP-CL31-IPC_C -585,-2255 r0 top value=10μF
C82 "CL31B106KAHSFNE" FP-CL31-IPC_C 585,-2255 r180 top value=10μF
C83 "CL10C560JB8NNNC" FP-C0603C-CF-IPC_B 1360,-2320 r0 top value=56pF
C84 "12063C225K4T2A" FP-CL31-IPC_C -585,-2337 r0 top value=2.2μF
C85 "CL31B106KAHSFNE" FP-CL31-IPC_C 585,-2337 r0 top value=10μF
C86 "GRT188R61H225ME13D" FP-C0603C-CF-IPC_B -1360,-2388 r180 top value=2.2μF
C87 "C0603C104K3RACTU" FP-C0603C-CF-IPC_B -4872,3325 r270 bottom value=0.10μF
C88 "C0603C472K3RAC7867" FP-C0603C-CF-IPC_B -5350,3325 r270 bottom value=4.7nF
C89 "GRT188R61H225ME13D" FP-C0603C-CF-IPC_B 1370,2558 r180 bottom value=2.2μF
C90 "GRT188R61H225ME13D" FP-C0603C-CF-IPC_B -1370,2558 r0 bottom value=2.2μF
C91 "CL10C560JB8NNNC" FP-C0603C-CF-IPC_B 1370,2490 r180 bottom value=56pF
C92 "CL10C560JB8NNNC" FP-C0603C-CF-IPC_B -1370,2490 r180 bottom value=56pF
C93 "CL31B106KAHSFNE" FP-CL31-IPC_C 540,2310 r270 bottom value=10μF
C94 "12063C225K4T2A" FP-CL31-IPC_C -540,2292 r90 bottom value=2.2μF
C95 "CL31B106KAHSFNE" FP-CL31-IPC_C -620,2292 r90 bottom value=10μF
C96 "CGA3E2X7R1H104K080AA" FP-C0603C-CF-IPC_B -700,2292 r90 bottom value=100nF
C97 "CL31B106KAHSFNE" FP-CL31-IPC_C -1370,2269 r180 bottom value=10μF
C99 "CL31B106KAHSFNE" FP-CL31-IPC_C -1370,2184 r180 bottom value=10μF
C100 "C0603C331JAGAC7867" FP-C0603C-CF-IPC_B 405,2141 r270 bottom value=330pF
C101 "CGA3E2X7R1H104K080AA" FP-C0603C-CF-IPC_B 1370,2150 r0 bottom value=100nF
C102 "CL31B106KAHSFNE" FP-CL31-IPC_B -4515,2075 r270 bottom value=10μF
C103 "CL31B106KAHSFNE" FP-CL31-IPC_B -4915,2075 r270 bottom value=10μF
C104 "CL31B106KAHSFNE" FP-CL31-IPC_C 610,2073 r90 bottom value=10μF
C105 "C0603C331JAGAC7867" FP-C0603C-CF-IPC_B -500,2107 r0 bottom value=330pF
C106 "CGA3E2X7R1H104K080AA" FP-C0603C-CF-IPC_B -1370,2099 r180 bottom value=100nF
C107 "CGA3E2X7R1H104K080AA" FP-C0603C-CF-IPC_B 722,2073 r270 bottom value=100nF
C108 "CL31B106KAHSFNE" FP-CL31-IPC_C 1370,2065 r0 bottom value=10μF
C109 "C0603C331JAGAC7867" FP-C0603C-CF-IPC_B 500,2039 r180 bottom value=330pF
C111 "C0603C331JAGAC7867" FP-C0603C-CF-IPC_B -405,2005 r90 bottom value=330pF
C112 "CL31B106KAHSFNE" FP-CL31-IPC_C 1370,1980 r0 bottom value=10μF
C113 "CL31B106KAHSFNE" FP-CL31-IPC_B -4515,1875 r90 bottom value=10μF
C114 "CL31B106KAHSFNE" FP-CL31-IPC_B -4915,1875 r90 bottom value=10μF
C115 "GRT188R61H225ME13D" FP-C0603C-CF-IPC_B 1370,1704 r180 bottom value=2.2μF
C116 "CL10C560JB8NNNC" FP-C0603C-CF-IPC_B -1500,1704 r180 bottom value=56pF
C117 "CL10C560JB8NNNC" FP-C0603C-CF-IPC_B 1500,1636 r0 bottom value=56pF
C118 "CL10C560JB8NNNC" FP-C0603C-CF-IPC_B -1500,1636 r180 bottom value=56pF
C119 "CL10C560JB8NNNC" FP-C0603C-CF-IPC_B 1500,1568 r0 bottom value=56pF
C120 "CL10C560JB8NNNC" FP-C0603C-CF-IPC_B -1500,1568 r180 bottom value=56pF
C121 "CL10C560JB8NNNC" FP-C0603C-CF-IPC_B 1500,1500 r0 bottom value=56pF
C122 "CL10C560JB8NNNC" FP-C0603C-CF-IPC_B -1500,1500 r180 bottom value=56pF
C123 "CL10C560JB8NNNC" FP-C0603C-CF-IPC_B 1500,1432 r0 bottom value=56pF
C124 "CL10C560JB8NNNC" FP-C0603C-CF-IPC_B -1500,1432 r180 bottom value=56pF
C125 "CL10C560JB8NNNC" FP-C0603C-CF-IPC_B 1500,1364 r0 bottom value=56pF
C126 "CL10C560JB8NNNC" FP-C0603C-CF-IPC_B -1500,1364 r180 bottom value=56pF
C127 "CL10C560JB8NNNC" FP-C0603C-CF-IPC_B 1500,1296 r0 bottom value=56pF
C128 "GRT188R61H225ME13D" FP-C0603C-CF-IPC_B -1370,1296 r0 bottom value=2.2μF
C129 "CL31B106KAHSFNE" FP-CL31-IPC_C -1370,1020 r180 bottom value=10μF
C130 "C0603C331JAGAC7867" FP-C0603C-CF-IPC_B 405,995 r270 bottom value=330pF
C132 "CL31B106KAHSFNE" FP-CL31-IPC_C -610,927 r270 bottom value=10μF
C133 "C0603C331JAGAC7867" FP-C0603C-CF-IPC_B -500,961 r0 bottom value=330pF
C134 "CGA3E2X7R1H104K080AA" FP-C0603C-CF-IPC_B -722,927 r90 bottom value=100nF
C135 "CL31B106KAHSFNE" FP-CL31-IPC_C -1370,935 r180 bottom value=10μF
C137 "CGA3E2X7R1H104K080AA" FP-C0603C-CF-IPC_B 1370,901 r0 bottom value=100nF
C138 "C0603C331JAGAC7867" FP-C0603C-CF-IPC_B 500,893 r180 bottom value=330pF
C139 "C0603C331JAGAC7867" FP-C0603C-CF-IPC_B -405,859 r90 bottom value=330pF
C140 "CGA3E2X7R1H104K080AA" FP-C0603C-CF-IPC_B -1370,850 r180 bottom value=100nF
C141 "CL31B106KAHSFNE" FP-CL31-IPC_C 1370,816 r0 bottom value=10μF
C142 "GRT188R61H225ME13D" FP-C0603C-CF-IPC_B -3200,804 r180 bottom value=2.2μF
C144 "CL31B106KAHSFNE" FP-CL31-IPC_C 620,708 r270 bottom value=10μF
C145 "12063C225K4T2A" FP-CL31-IPC_C 540,708 r270 bottom value=2.2μF
C146 "CL31B106KAHSFNE" FP-CL31-IPC_C 1370,731 r0 bottom value=10μF
C148 "CGA3E2X7R1H104K080AA" FP-C0603C-CF-IPC_B 700,708 r270 bottom value=100nF
C149 "CL31B106KAHSFNE" FP-CL31-IPC_C -540,690 r90 bottom value=10μF
C150 "CGA3E2X7R1H104K080AA" FP-C0603C-CF-IPC_B -790,515 r270 bottom value=100nF
C151 "CL10C560JB8NNNC" FP-C0603C-CF-IPC_B -2800,532 r180 bottom value=56pF
C152 "CL10C560JB8NNNC" FP-C0603C-CF-IPC_B 1370,510 r0 bottom value=56pF
C153 "CL10C560JB8NNNC" FP-C0603C-CF-IPC_B -1370,510 r180 bottom value=56pF
C154 "CL10C560JB8NNNC" FP-C0603C-CF-IPC_B -2800,464 r180 bottom value=56pF
C155 "GRT188R61H225ME13D" FP-C0603C-CF-IPC_B -3200,464 r180 bottom value=2.2μF
C156 "CL10C101JB8NNNC" FP-C0603C-CF-IPC_B -4100,464 r0 bottom value=100pF
C157 "GRT188R61H225ME13D" FP-C0603C-CF-IPC_B 1370,442 r180 bottom value=2.2μF
C158 "GRT188R61H225ME13D" FP-C0603C-CF-IPC_B -1370,442 r0 bottom value=2.2μF
C159 "CL10C560JB8NNNC" FP-C0603C-CF-IPC_B -2800,396 r180 bottom value=56pF
C160 "CL10C560JB8NNNC" FP-C0603C-CF-IPC_B -3200,396 r180 bottom value=56pF
C161 "CL10C101JB8NNNC" FP-C0603C-CF-IPC_B -4250,396 r180 bottom value=100pF
C162 "GRT188R61H225ME13D" FP-C0603C-CF-IPC_B -2000,328 r180 bottom value=2.2μF
C163 "CL10C560JB8NNNC" FP-C0603C-CF-IPC_B -2800,328 r180 bottom value=56pF
C164 "GRT188R61H225ME13D" FP-C0603C-CF-IPC_B -3200,328 r0 bottom value=2.2μF
C165 "GRT188R61H225ME13D" FP-C0603C-CF-IPC_B -2000,260 r0 bottom value=2.2μF
C166 "GRT188R61H225ME13D" FP-C0603C-CF-IPC_B -3200,260 r180 bottom value=2.2μF
C167 "CL10C101JB8NNNC" FP-C0603C-CF-IPC_B -3600,260 r0 bottom value=100pF
C168 "C0603C104K3RACTU" FP-C0603C-CF-IPC_B -4100,260 r180 bottom value=0.10μF
C169 "CL10C101JB8NNNC" FP-C0603C-CF-IPC_B -4100,192 r0 bottom value=100pF
C170 "CGA3E1X7R1V105K080AC" FP-C0603C-CF-IPC_B 640,136 r180 bottom value=1μF
C171 "CL10C101JB8NNNC" FP-C0603C-CF-IPC_B -4100,124 r0 bottom value=100pF
C172 "GCM188R71H102KA37D" FP-C0603C-CF-IPC_B 640,68 r180 bottom value=1nF
C173 "CL10C101JB8NNNC" FP-C0603C-CF-IPC_B -4250,56 r180 bottom value=100pF
C174 "CGA3E2X7R1H104K080AA" FP-C0603C-CF-IPC_B 640,0 r180 bottom value=100nF
C175 "GCM188R71H102KA37D" FP-C0603C-CF-IPC_B -640,0 r0 bottom value=1nF
C176 "CL10C560JB8NNNC" FP-C0603C-CF-IPC_B -2800,-12 r180 bottom value=56pF
C177 "CGA3E2X7R1H104K080AA" FP-C0603C-CF-IPC_B -640,-68 r0 bottom value=100nF
C178 "GRT188R61H225ME13D" FP-C0603C-CF-IPC_B -2800,-80 r180 bottom value=2.2μF
C179 "CL10C560JB8NNNC" FP-C0603C-CF-IPC_B -3200,-80 r180 bottom value=56pF
C180 "CL10C101JB8NNNC" FP-C0603C-CF-IPC_B -3600,-80 r0 bottom value=100pF
C181 "C0603C104K3RACTU" FP-C0603C-CF-IPC_B -4100,-80 r180 bottom value=0.10μF
C182 "CGA3E1X7R1V105K080AC" FP-C0603C-CF-IPC_B -640,-136 r0 bottom value=1μF
C183 "CL10C560JB8NNNC" FP-C0603C-CF-IPC_B -3200,-148 r180 bottom value=56pF
C184 "CL10C101JB8NNNC" FP-C0603C-CF-IPC_B -4100,-148 r0 bottom value=100pF
C185 "CL10C560JB8NNNC" FP-C0603C-CF-IPC_B -3200,-216 r180 bottom value=56pF
C186 "CL10C101JB8NNNC" FP-C0603C-CF-IPC_B -4100,-216 r0 bottom value=100pF
C187 "GRT188R61H225ME13D" FP-C0603C-CF-IPC_B -3200,-284 r180 bottom value=2.2μF
C188 "CL10C101JB8NNNC" FP-C0603C-CF-IPC_B -4250,-284 r180 bottom value=100pF
C189 "CGA3E1X7R1V105K080AC" FP-C0603C-CF-IPC_B -2800,-352 r0 bottom value=1μF
C190 "GCM188R71C274KA37D" FP-C0603C-CF-IPC_B -3200,-352 r180 bottom value=270nF
C191 "CGA3E1X7R1V105K080AC" FP-C0603C-CF-IPC_B -2799.96,-420 r0 bottom value=1μF
C192 "CL10C101JB8NNNC" FP-C0603C-CF-IPC_B -3600,-420 r0 bottom value=100pF
C193 "C0603C104K3RACTU" FP-C0603C-CF-IPC_B -4100,-420 r180 bottom value=0.10μF
C194 "GRT188R61H225ME13D" FP-C0603C-CF-IPC_B 1370,-442 r180 bottom value=2.2μF
C195 "GRT188R61H225ME13D" FP-C0603C-CF-IPC_B -1370,-442 r0 bottom value=2.2μF
C196 "CL10C101JB8NNNC" FP-C0603C-CF-IPC_B -4100,-488 r0 bottom value=100pF
C197 "CL10C560JB8NNNC" FP-C0603C-CF-IPC_B 1370,-510 r0 bottom value=56pF
C198 "CL10C560JB8NNNC" FP-C0603C-CF-IPC_B -1370,-510 r180 bottom value=56pF
C199 "GCM188R71C274KA37D" FP-C0603C-CF-IPC_B -3200,-556 r180 bottom value=270nF
C200 "CL10C101JB8NNNC" FP-C0603C-CF-IPC_B -4100,-556 r0 bottom value=100pF
C201 "GCM1885C2A221JA16D" FP-C0603C-CF-IPC_B -2800,-624 r0 bottom value=220pF
C202 "GCM188R71C274KA37D" FP-C0603C-CF-IPC_B -3200,-624 r180 bottom value=270nF
C203 "CL10C101JB8NNNC" FP-C0603C-CF-IPC_B -4250,-624 r180 bottom value=100pF
C204 "CL31B106KAHSFNE" FP-CL31-IPC_C 540,-690 r270 bottom value=10μF
C205 "12063C225K4T2A" FP-CL31-IPC_C -540,-708 r90 bottom value=2.2μF
C206 "CL31B106KAHSFNE" FP-CL31-IPC_C -620,-708 r90 bottom value=10μF
C207 "CGA3E2X7R1H104K080AA" FP-C0603C-CF-IPC_B -700,-708 r90 bottom value=100nF
C208 "CL31B106KAHSFNE" FP-CL31-IPC_C -1370,-731 r180 bottom value=10μF
C209 "GCM1885C2A221JA16D" FP-C0603C-CF-IPC_B -2800,-760 r0 bottom value=220pF
C210 "CL10C101JB8NNNC" FP-C0603C-CF-IPC_B -3600,-760 r0 bottom value=100pF
C211 "C0603C104K3RACTU" FP-C0603C-CF-IPC_B -4100,-760 r180 bottom value=0.10μF
C213 "CL31B106KAHSFNE" FP-CL31-IPC_C -1370,-816 r180 bottom value=10μF
C214 "GCM188R71C274KA37D" FP-C0603C-CF-IPC_B -3200,-828 r180 bottom value=270nF
C215 "CL10C101JB8NNNC" FP-C0603C-CF-IPC_B -4100,-828 r0 bottom value=100pF
C216 "C0603C331JAGAC7867" FP-C0603C-CF-IPC_B 405,-859 r270 bottom value=330pF
C217 "CGA3E2X7R1H104K080AA" FP-C0603C-CF-IPC_B 1370,-850 r0 bottom value=100nF
C218 "CL31B106KAHSFNE" FP-CL31-IPC_C 610,-927 r90 bottom value=10μF
C219 "C0603C331JAGAC7867" FP-C0603C-CF-IPC_B -500,-893 r0 bottom value=330pF
C220 "CGA3E2X7R1H104K080AA" FP-C0603C-CF-IPC_B -1370,-901 r180 bottom value=100nF
C221 "CGA3E2X7R1H104K080AA" FP-C0603C-CF-IPC_B 722,-927 r270 bottom value=100nF
C222 "CL31B106KAHSFNE" FP-CL31-IPC_C 1370,-935 r0 bottom value=10μF
C223 "C0603C331JAGAC7867" FP-C0603C-CF-IPC_B 500,-961 r180 bottom value=330pF
C224 "CL10C560JB8NNNC" FP-C0603C-CF-IPC_B -2800,-964 r180 bottom value=56pF
C226 "C0603C331JAGAC7867" FP-C0603C-CF-IPC_B -405,-995 r90 bottom value=330pF
C227 "CL31B106KAHSFNE" FP-CL31-IPC_C 1370,-1020 r0 bottom value=10μF
C228 "CL10C560JB8NNNC" FP-C0603C-CF-IPC_B -2800,-1032 r180 bottom value=56pF
C229 "CL10C560JB8NNNC" FP-C0603C-CF-IPC_B -2800,-1100 r180 bottom value=56pF
C230 "CL10C560JB8NNNC" FP-C0603C-CF-IPC_B -2800,-1168 r180 bottom value=56pF
C231 "GRT188R61H225ME13D" FP-C0603C-CF-IPC_B 1370,-1296 r180 bottom value=2.2μF
C232 "CL10C560JB8NNNC" FP-C0603C-CF-IPC_B -1500,-1296 r180 bottom value=56pF
C233 "CL10C560JB8NNNC" FP-C0603C-CF-IPC_B 1500,-1364 r0 bottom value=56pF
C234 "CL10C560JB8NNNC" FP-C0603C-CF-IPC_B -1500,-1364 r180 bottom value=56pF
C235 "CL10C560JB8NNNC" FP-C0603C-CF-IPC_B -2800,-1372 r180 bottom value=56pF
C236 "CL10C560JB8NNNC" FP-C0603C-CF-IPC_B 1500,-1432 r0 bottom value=56pF
C237 "CL10C560JB8NNNC" FP-C0603C-CF-IPC_B -1500,-1432 r180 bottom value=56pF
C238 "CL10C560JB8NNNC" FP-C0603C-CF-IPC_B -2800,-1440 r180 bottom value=56pF
C239 "CL10C560JB8NNNC" FP-C0603C-CF-IPC_B 1500,-1500 r0 bottom value=56pF
C240 "CL10C560JB8NNNC" FP-C0603C-CF-IPC_B -1500,-1500 r180 bottom value=56pF
C241 "CL10C560JB8NNNC" FP-C0603C-CF-IPC_B -2800,-1508 r180 bottom value=56pF
C242 "CL10C560JB8NNNC" FP-C0603C-CF-IPC_B 1500,-1568 r0 bottom value=56pF
C243 "CL10C560JB8NNNC" FP-C0603C-CF-IPC_B -1500,-1568 r180 bottom value=56pF
C244 "CL10C560JB8NNNC" FP-C0603C-CF-IPC_B 1500,-1636 r0 bottom value=56pF
C245 "CL10C560JB8NNNC" FP-C0603C-CF-IPC_B -1500,-1636 r180 bottom value=56pF
C246 "CL10C560JB8NNNC" FP-C0603C-CF-IPC_B 1500,-1704 r0 bottom value=56pF
C247 "GRT188R61H225ME13D" FP-C0603C-CF-IPC_B -1370,-1704 r0 bottom value=2.2μF
C248 "CL31B106KAHSFNE" FP-CL31-IPC_C -1370,-1980 r180 bottom value=10μF
C249 "C0603C331JAGAC7867" FP-C0603C-CF-IPC_B 405,-2005 r270 bottom value=330pF
C251 "CL31B106KAHSFNE" FP-CL31-IPC_C -610,-2073 r270 bottom value=10μF
C252 "C0603C331JAGAC7867" FP-C0603C-CF-IPC_B -500,-2039 r0 bottom value=330pF
C253 "CGA3E2X7R1H104K080AA" FP-C0603C-CF-IPC_B -722,-2073 r90 bottom value=100nF
C254 "CL31B106KAHSFNE" FP-CL31-IPC_C -1370,-2065 r180 bottom value=10μF
C255 "CGA3E2X7R1H104K080AA" FP-C0603C-CF-IPC_B 1370,-2099 r0 bottom value=100nF
C256 "C0603C331JAGAC7867" FP-C0603C-CF-IPC_B 500,-2107 r180 bottom value=330pF
C257 "C0603C331JAGAC7867" FP-C0603C-CF-IPC_B -405,-2141 r90 bottom value=330pF
C258 "CGA3E2X7R1H104K080AA" FP-C0603C-CF-IPC_B -1370,-2150 r180 bottom value=100nF
C259 "CL31B106KAHSFNE" FP-CL31-IPC_C 1370,-2184 r0 bottom value=10μF
C261 "CL31B106KAHSFNE" FP-CL31-IPC_C 620,-2292 r270 bottom value=10μF
C262 "12063C225K4T2A" FP-CL31-IPC_C 540,-2292 r270 bottom value=2.2μF
C263 "CL31B106KAHSFNE" FP-CL31-IPC_C 1370,-2269 r0 bottom value=10μF
C264 "CGA3E2X7R1H104K080AA" FP-C0603C-CF-IPC_B 700,-2292 r270 bottom value=100nF
C265 "CL31B106KAHSFNE" FP-CL31-IPC_C -540,-2310 r90 bottom value=10μF
C266 "CGA3E2X7R1H104K080AA" FP-C0603C-CF-IPC_B -790,-2485 r270 bottom value=100nF
C267 "CL10C560JB8NNNC" FP-C0603C-CF-IPC_B 1370,-2490 r0 bottom value=56pF
C268 "CL10C560JB8NNNC" FP-C0603C-CF-IPC_B -1370,-2490 r180 bottom value=56pF
C269 "GRT188R61H225ME13D" FP-C0603C-CF-IPC_B 1370,-2558 r180 bottom value=2.2μF
C270 "GRT188R61H225ME13D" FP-C0603C-CF-IPC_B -1370,-2558 r180 bottom value=2.2μF
D1 "LTST-C171GKT" FP-LTST-C171GKT-MFG -4100,2375 r270 top value=GREEN
D2 "LTST-C171GKT" FP-LTST-C171GKT-MFG -3800,2375 r270 top value=GREEN
D3 "LTST-C171GKT" FP-LTST-C171GKT-MFG -3500,2375 r270 top value=GREEN
D4 "BAT42W-TP" SOD3716X135N -600,1945 r0 top value=N/A
D5 "BAT42W-TP" SOD3716X135N 600,1945 r180 top value=N/A
D6 "HSMC-C170" FP-LTST-C171GKT-MFG-RED -1360,1836 r0 top value=RED
D7 "HSMC-C170" FP-LTST-C171GKT-MFG-RED 1360,1836 r180 top value=RED
D8 "US3M-13" DIOM6959X25N -475,1690 r180 top value=N/A
D9 "US3M-13" DIOM6959X25N 475,1690 r0 top value=N/A
D10 "US3M-13" DIOM6959X25N -475,1310 r180 top value=N/A
D11 "US3M-13" DIOM6959X25N 475,1310 r0 top value=N/A
D12 "HSMC-C170" FP-LTST-C171GKT-MFG-RED -1360,1164 r0 top value=RED
D13 "HSMC-C170" FP-LTST-C171GKT-MFG-RED 1360,1164 r180 top value=RED
D14 "BAT42W-TP" SOD3716X135N -600,1055 r0 top value=N/A
D15 "BAT42W-TP" SOD3716X135N 600,1055 r180 top value=N/A
D16 "HSMC-C170" FP-LTST-C171GKT-MFG-RED -2400,600 r180 top value=RED
D17 "LTST-C171KSKT" FP-LTST-C171GKT-MFG-YELLOW -2400,517 r180 top value=YELLOW
D18 "LTST-C171GKT" FP-LTST-C171GKT-MFG -2400,434 r180 top value=GREEN
D19 "BAT42W-TP" SOD3716X135N -600,-1055 r0 top value=N/A
D20 "BAT42W-TP" SOD3716X135N 600,-1055 r180 top value=N/A
D21 "HSMC-C170" FP-LTST-C171GKT-MFG-RED -1360,-1164 r0 top value=RED
D22 "HSMC-C170" FP-LTST-C171GKT-MFG-RED 1360,-1164 r180 top value=RED
D23 "US3M-13" DIOM6959X25N -475,-1310 r180 top value=N/A
D24 "US3M-13" DIOM6959X25N 475,-1310 r0 top value=N/A
D25 "US3M-13" DIOM6959X25N -475,-1690 r180 top value=N/A
D26 "US3M-13" DIOM6959X25N 475,-1690 r0 top value=N/A
D27 "HSMC-C170" FP-LTST-C171GKT-MFG-RED -1360,-1836 r0 top value=RED
D28 "HSMC-C170" FP-LTST-C171GKT-MFG-RED 1360,-1836 r180 top value=RED
D29 "BAT42W-TP" SOD3716X135N -600,-1945 r0 top value=N/A
D30 "BAT42W-TP" SOD3716X135N 600,-1945 r180 top value=N/A
D31 "APTR3216-VFX" FP-APTR3216SECK-MFG -500,3700 r0 bottom value=PURPLE
D32 "APTR3216-VFX" FP-APTR3216SECK-MFG -3100,3700 r180 bottom value=PURPLE
D33 "US3M-13" DIOM6959X25N 700,1715 r0 bottom value=N/A
D34 "US3M-13" DIOM6959X25N -700,1715 r180 bottom value=N/A
D35 "US3M-13" DIOM6959X25N 700,1285 r0 bottom value=N/A
D36 "US3M-13" DIOM6959X25N -700,1285 r180 bottom value=N/A
D37 "US3M-13" DIOM6959X25N 700,-1285 r0 bottom value=N/A
D38 "US3M-13" DIOM6959X25N -700,-1285 r180 bottom value=N/A
D39 "US3M-13" DIOM6959X25N 700,-1715 r0 bottom value=N/A
D40 "US3M-13" DIOM6959X25N -700,-1715 r180 bottom value=N/A
D41 "APTR3216-VFX" FP-APTR3216SECK-MFG -500,-3700 r0 bottom value=PURPLE
D42 "APTR3216-VFX" FP-APTR3216SECK-MFG -3100,-3700 r180 bottom value=PURPLE
J1 "640456-2" TECO-640456-2_V -2800,3850 r180 top value=N/A
J2 "0734151471" FP-73415-1471-MFG -405,2300 r90 top value=N/A
J3 "0734151471" FP-73415-1471-MFG 405,2300 r90 top value=N/A
J4 "0734151471" FP-73415-1471-MFG -405,700 r270 top locked value=N/A
J5 "0734151471" FP-73415-1471-MFG 405,700 r270 top locked value=N/A
J6 "0734151471" FP-73415-1471-MFG -405,-700 r90 top value=N/A
J7 "0734151471" FP-73415-1471-MFG 405,-700 r90 top value=N/A
J8 "61301221121" FP-61301221121-MFG -2000,-1255 r270 top value=N/A
J9 "0734151471" FP-73415-1471-MFG -405,-2300 r270 top locked value=N/A
J10 "0734151471" FP-73415-1471-MFG 405,-2300 r270 top locked value=N/A
J11 "PJ-102AH" CUI-PJ-102B_V -4240,3565 r90 bottom locked value=N/A
J12 "L717SDE09PA4CH4RC309" L717SDE09PA4CH4RC309 -5125,3625 r0 bottom locked value=N/A
J13 "2082940040" 2082940040 -6075,3120 r90 bottom value=N/A
J14 "SSW-126-01-G-D (X2)" SAMTEC_SSW-126-01-G-D_DUAL_CUSTOM 0,0 r90 bottom value=N/A
L1 "DLW43SH101XK2L" FP-DLW43-0_2-t2_6-e0_6-MFG -5100,3325 r180 top value=100µH
MH1 "MH_M4_NP" MH_M4_NP -6050,3750 r0 top value=N/A
MH2 "MH_M4_P" MH_M4_P -1043.31,3750 r0 top value=N/A
MH3 "MH_M4_P" MH_M4_P 1043.31,3750 r0 top value=N/A
MH4 "MH_M4_NP" MH_M4_NP 2450,3750 r0 top value=N/A
MH5 "MH_M4_NP" MH_M4_NP -6050,-3750 r0 top value=N/A
MH6 "MH_M4_P" MH_M4_P -1043.31,-3750 r0 top value=N/A
MH7 "MH_M4_P" MH_M4_P 1043.31,-3750 r0 top value=N/A
MH8 "MH_M4_NP" MH_M4_NP 2450,-3750 r0 top value=N/A
Q1 "DMT12H007LPS-13" FP-PowerDI5060-8-MFG -3840,3785 r90 top value=N/A
Q2 "DMT12H007LPS-13" FP-PowerDI5060-8-MFG -3840,3485 r90 top value=N/A
R1 "RC0603FR-07100KL" FP-MCR03-IPC_B -3543,3845 r90 top value=100kΩ
R2 "RC0603FR-07100KL" FP-MCR03-IPC_B -3475,3845 r270 top value=100kΩ
R3 "RC0603FR-07100KL" FP-MCR03-IPC_B -3407,3845 r270 top value=100kΩ
R4 "RC0603JR-072M7L" FP-MCR03-IPC_B -3339,3845 r90 top value=2.7MΩ
R5 "CRCW12100000Z0EAHP" RESC3125X70X40NL20T20 -1430,3805 r0 top value=0Ω
R6 "CRCW12100000Z0EAHP" RESC3125X70X40NL20T20 -1430,3675 r0 top value=0Ω
R7 "RC0603JR-072M7L" FP-MCR03-IPC_B -3611,3425 r270 top value=2.7MΩ
R8 "RC0603FR-07100KL" FP-MCR03-IPC_B -3543,3425 r270 top value=100kΩ
R9 "CRCW060320K0FKTA" FP-MCR03-IPC_B -3475,3425 r90 top value=20kΩ
R10 "RT0603DRE072KL" FP-MCR03-IPC_B -3407,3425 r270 top value=2kΩ
R11 "RC0603JR-07120RL" FP-MCR03-IPC_B -5350,3400 r270 top value=120Ω
R12 "RC0603JR-07120RL" FP-MCR03-IPC_B -5282,3400 r270 top value=120Ω
R13 "PE2512FKE7W0R01L" FP-RL2512-IPC_A -3840,3155 r270 top value=10mΩ
R14 "RC0603JR-07120RL" FP-MCR03-IPC_B -5350,3250 r270 top value=120Ω
R15 "RC0603JR-07120RL" FP-MCR03-IPC_B -5282,3250 r270 top value=120Ω
R16 "RC0603JR-07120RL" FP-MCR03-IPC_B -1360,2388 r0 top value=120Ω
R17 "RC0603JR-07120RL" FP-MCR03-IPC_B 1360,2320 r180 top value=120Ω
R18 "RC0603JR-07120RL" FP-MCR03-IPC_B -1360,2252 r0 top value=120Ω
R19 "CRCW06030000Z0EB" FP-MCR03-IPC_B -585,2170 r0 top value=0Ω
R20 "CRCW06030000Z0EB" FP-MCR03-IPC_B 585,2170 r180 top value=0Ω
R21 "CRCW12100000Z0EAHP" RESC3125X70X40NL20T20 -415,2137 r0 top value=0Ω
R22 "RCWE1210R910FKEA" RESC3125X70X40NL20T20 415,2137 r180 top value=0.91Ω
R23 "RC0603JR-07120RL" FP-MCR03-IPC_B 1360,2048 r180 top value=120Ω
R24 "RCWE1210R910FKEA" RESC3125X70X40NL20T20 -415,2013 r0 top value=0.91Ω
R25 "CRCW12100000Z0EAHP" RESC3125X70X40NL20T20 415,2013 r180 top value=0Ω
R26 "RC0603JR-07120RL" FP-MCR03-IPC_B -1360,1980 r0 top value=120Ω
R27 "RC0603JR-07120RL" FP-MCR03-IPC_B 1360,1912 r180 top value=120Ω
R28 "RT0603FRE07220RL" FP-MCR03-IPC_B -815,1821 r0 top value=220Ω
R29 "RT0603FRE07220RL" FP-MCR03-IPC_B 815,1821 r180 top value=220Ω
R30 "RC0603FR-102K2L" FP-MCR03-IPC_B -815,1753 r180 top value=2.2kΩ
R31 "RC0603FR-102K2L" FP-MCR03-IPC_B 815,1753 r0 top value=2.2kΩ
R32 "RC0603FR-102K2L" FP-MCR03-IPC_B -815,1685 r0 top value=2.2kΩ
R33 "RC0603FR-102K2L" FP-MCR03-IPC_B 815,1685 r180 top value=2.2kΩ
R34 "RC0603FR-102K2L" FP-MCR03-IPC_B -815,1315 r0 top value=2.2kΩ
R35 "RC0603FR-102K2L" FP-MCR03-IPC_B 815,1315 r180 top value=2.2kΩ
R36 "RC0603FR-102K2L" FP-MCR03-IPC_B -815,1247 r180 top value=2.2kΩ
R37 "RC0603FR-102K2L" FP-MCR03-IPC_B 815,1247 r0 top value=2.2kΩ
R38 "RT0603FRE07220RL" FP-MCR03-IPC_B -815,1179 r0 top value=220Ω
R39 "RT0603FRE07220RL" FP-MCR03-IPC_B 815,1179 r180 top value=220Ω
R40 "RC0603JR-07120RL" FP-MCR03-IPC_B -1360,1088 r0 top value=120Ω
R41 "ERJ3EKF1002V" FP-MCR03-IPC_B -2400,1076 r0 top value=10kΩ
R42 "RC0603JR-07120RL" FP-MCR03-IPC_B 1360,1020 r180 top value=120Ω
R43 "CRCW12100000Z0EAHP" RESC3125X70X40NL20T20 -415,987 r0 top value=0Ω
R44 "RCWE1210R910FKEA" RESC3125X70X40NL20T20 415,987 r180 top value=0.91Ω
R45 "RC0603JR-07120RL" FP-MCR03-IPC_B -2800,1008 r0 top value=120Ω
R46 "RC0603JR-07120RL" FP-MCR03-IPC_B -1360,952 r0 top value=120Ω
R47 "ERJ3EKF1002V" FP-MCR03-IPC_B -2800,940 r180 top value=10kΩ
R48 "RCWE1210R910FKEA" RESC3125X70X40NL20T20 -415,863 r0 top value=0.91Ω
R49 "CRCW12100000Z0EAHP" RESC3125X70X40NL20T20 415,863 r180 top value=0Ω
R50 "CRCW06030000Z0EB" FP-MCR03-IPC_B -585,830 r0 top value=0Ω
R51 "CRCW06030000Z0EB" FP-MCR03-IPC_B 585,830 r180 top value=0Ω
R52 "RC0603JR-07120RL" FP-MCR03-IPC_B -2800,804 r0 top value=120Ω
R53 "RC0603JR-07120RL" FP-MCR03-IPC_B 1360,748 r180 top value=120Ω
R55 "RC0603JR-07120RL" FP-MCR03-IPC_B -1360,680 r0 top value=120Ω
R57 "RC0603JR-07120RL" FP-MCR03-IPC_B 1360,612 r180 top value=120Ω
R58 "RC0603FR-13330RL" FP-MCR03-IPC_B -2800,600 r180 top value=330Ω
R59 "RC0603FR-13330RL" FP-MCR03-IPC_B -2800,532 r180 top value=330Ω
R60 "RC0603FR-13330RL" FP-MCR03-IPC_B -2800,464 r180 top value=330Ω
R61 "RC0603FR-13330RL" FP-MCR03-IPC_B -2800,396 r180 top value=330Ω
R62 "RC0603JR-07120RL" FP-MCR03-IPC_B -2400,328 r0 top value=120Ω
R63 "RC0603JR-07120RL" FP-MCR03-IPC_B -2400,260 r0 top value=120Ω
R64 "RNCF1206BKE1M00" RESC3116X65X40LL10T20 -595,250 r0 top value=1MΩ
R65 "RNCF1206BKE1M00" RESC3116X65X40LL10T20 -385,250 r0 top value=1MΩ
R66 "RNCF1206BKE1M00" RESC3116X65X40LL10T20 -175,250 r0 top value=1MΩ
R67 "CRCW06030000Z0EB" FP-MCR03-IPC_B -1360,204 r180 top value=0Ω
R68 "RC0603JR-07120RL" FP-MCR03-IPC_B -2400,192 r0 top value=120Ω
R69 "ERJ3EKF1002V" FP-MCR03-IPC_B 1360,136 r0 top value=10kΩ
R70 "CRCW06030000Z0EB" FP-MCR03-IPC_B -1360,68 r180 top value=0Ω
R71 "CRCW06030000Z0EB" FP-MCR03-IPC_B -640,68 r180 top value=0Ω
R72 "CRCW06030000Z0EB" FP-MCR03-IPC_B 640,68 r0 top value=0Ω
R73 "RC0603JR-07120RL" FP-MCR03-IPC_B -2400,56 r0 top value=120Ω
R74 "ERJ-3EKF49R9V" FP-MCR03-IPC_B -2800.05,-12 r0 top value=49.9Ω
R75 "RC0603FR-07100KL" FP-MCR03-IPC_B -2400,-12 r180 top value=100kΩ
R76 "CRCW06030000Z0EB" FP-MCR03-IPC_B -640,-68 r180 top value=0Ω
R77 "CRCW06030000Z0EB" FP-MCR03-IPC_B 640,-68 r0 top value=0Ω
R78 "CRCW06030000Z0EB" FP-MCR03-IPC_B 1360,-68 r0 top value=0Ω
R79 "RC0603FR-07100KL" FP-MCR03-IPC_B -2400,-80 r180 top value=100kΩ
R80 "ERJ3EKF1002V" FP-MCR03-IPC_B -1360,-136 r180 top value=10kΩ
R81 "RC0603FR-07100KL" FP-MCR03-IPC_B -2400,-148 r180 top value=100kΩ
R82 "CRCW06030000Z0EB" FP-MCR03-IPC_B 1360,-204 r0 top value=0Ω
R83 "RC0603FR-07100KL" FP-MCR03-IPC_B -2400,-216 r180 top value=100kΩ
R84 "RNCF1206BKE1M00" RESC3116X65X40LL10T20 175,-250 r180 top value=1MΩ
R85 "RNCF1206BKE1M00" RESC3116X65X40LL10T20 385,-250 r180 top value=1MΩ
R86 "RNCF1206BKE1M00" RESC3116X65X40LL10T20 595,-250 r180 top value=1MΩ
R87 "RC0603FR-07100KL" FP-MCR03-IPC_B -2400,-284 r180 top value=100kΩ
R88 "RC0603FR-07100KL" FP-MCR03-IPC_B -2400,-352 r180 top value=100kΩ
R89 "RC0603FR-07100KL" FP-MCR03-IPC_B -2800,-420 r0 top value=100kΩ
R90 "RC0603FR-07100KL" FP-MCR03-IPC_B -2400,-420 r180 top value=100kΩ
R91 "RC0603FR-07100KL" FP-MCR03-IPC_B -2800,-488 r0 top value=100kΩ
R92 "RC0603FR-07100KL" FP-MCR03-IPC_B -2400,-488 r180 top value=100kΩ
R93 "NCU18XH103F6SRB" FP-NCU18-0_15-IPC_B -2800,-556 r0 top value="10kΩ @25C"
R94 "RC0603JR-07120RL" FP-MCR03-IPC_B -1360,-612 r0 top value=120Ω
R95 "ERJ3EKF1002V" FP-MCR03-IPC_B -2400,-624 r0 top value=10kΩ
R96 "RC0603JR-07120RL" FP-MCR03-IPC_B 1360,-680 r180 top value=120Ω
R97 "CRCW06030000Z0EB" FP-MCR03-IPC_B -2800,-692 r0 top value=0Ω
R98 "ERJ3EKF1002V" FP-MCR03-IPC_B -2400,-692 r0 top value=10kΩ
R99 "RC0603JR-07120RL" FP-MCR03-IPC_B -1360,-748 r0 top value=120Ω
R100 "RC0603JR-1310RL" FP-MCR03-IPC_B -2800,-760 r180 top value=10Ω
R101 "RT0603DRD0716K5L" FP-MCR03-IPC_B -2400,-760 r180 top value=16.5kΩ
R102 "ERJ3EKF1002V" FP-MCR03-IPC_B -2400,-828 r0 top value=10kΩ
R103 "CRCW06030000Z0EB" FP-MCR03-IPC_B -585,-830 r0 top value=0Ω
R104 "CRCW06030000Z0EB" FP-MCR03-IPC_B 585,-830 r180 top value=0Ω
R105 "CRCW12100000Z0EAHP" RESC3125X70X40NL20T20 -415,-863 r0 top value=0Ω
R106 "RCWE1210R910FKEA" RESC3125X70X40NL20T20 415,-863 r180 top value=0.91Ω
R107 "RC0603JR-1310RL" FP-MCR03-IPC_B -2800,-896 r180 top value=10Ω
R108 "ERJ3EKF1002V" FP-MCR03-IPC_B -2400,-896 r0 top value=10kΩ
R109 "RC0603JR-07120RL" FP-MCR03-IPC_B 1360,-952 r180 top value=120Ω
R110 "RCWE1210R910FKEA" RESC3125X70X40NL20T20 -415,-987 r0 top value=0.91Ω
R111 "CRCW12100000Z0EAHP" RESC3125X70X40NL20T20 415,-987 r180 top value=0Ω
R112 "RT0603DRD0716K5L" FP-MCR03-IPC_B -2400,-964 r180 top value=16.5kΩ
R113 "RC0603JR-07120RL" FP-MCR03-IPC_B -1360,-1020 r0 top value=120Ω
R114 "CRCW06030000Z0EB" FP-MCR03-IPC_B -2800,-1032 r180 top value=0Ω
R115 "CRCW06030000Z0EB" FP-MCR03-IPC_B -2400,-1032 r180 top value=0Ω
R116 "RC0603JR-07120RL" FP-MCR03-IPC_B 1360,-1088 r180 top value=120Ω
R117 "CRCW06030000Z0EB" FP-MCR03-IPC_B -2800,-1100 r180 top value=0Ω
R118 "CRCW06030000Z0EB" FP-MCR03-IPC_B -2400,-1100 r180 top value=0Ω
R119 "CRCW06030000Z0EB" FP-MCR03-IPC_B -2800,-1168 r180 top value=0Ω
R120 "CRCW06030000Z0EB" FP-MCR03-IPC_B -2400,-1168 r180 top value=0Ω
R121 "RT0603FRE07220RL" FP-MCR03-IPC_B -815,-1179 r0 top value=220Ω
R122 "RT0603FRE07220RL" FP-MCR03-IPC_B 815,-1179 r180 top value=220Ω
R123 "CRCW06030000Z0EB" FP-MCR03-IPC_B -2800,-1236 r180 top value=0Ω
R124 "CRCW06030000Z0EB" FP-MCR03-IPC_B -2400,-1236 r180 top value=0Ω
R125 "RC0603FR-102K2L" FP-MCR03-IPC_B -815,-1247 r180 top value=2.2kΩ
R126 "RC0603FR-102K2L" FP-MCR03-IPC_B 815,-1247 r0 top value=2.2kΩ
R127 "CRCW06030000Z0EB" FP-MCR03-IPC_B -2800,-1304 r180 top value=0Ω
R128 "CRCW06030000Z0EB" FP-MCR03-IPC_B -2400,-1304 r180 top value=0Ω
R129 "RC0603FR-102K2L" FP-MCR03-IPC_B -815,-1315 r0 top value=2.2kΩ
R130 "RC0603FR-102K2L" FP-MCR03-IPC_B 815,-1315 r180 top value=2.2kΩ
R131 "CRCW06030000Z0EB" FP-MCR03-IPC_B -2800,-1372 r180 top value=0Ω
R132 "CRCW06030000Z0EB" FP-MCR03-IPC_B -2400,-1372 r180 top value=0Ω
R133 "CRCW06030000Z0EB" FP-MCR03-IPC_B -2800,-1440 r180 top value=0Ω
R134 "CRCW06030000Z0EB" FP-MCR03-IPC_B -2400,-1440 r180 top value=0Ω
R135 "CRCW06030000Z0EB" FP-MCR03-IPC_B -2800,-1508 r180 top value=0Ω
R136 "CRCW06030000Z0EB" FP-MCR03-IPC_B -2400,-1508 r180 top value=0Ω
R137 "ERJ3EKF1002V" FP-MCR03-IPC_B -2800,-1576 r180 top value=10kΩ
R138 "RC0603FR-102K2L" FP-MCR03-IPC_B -815,-1685 r0 top value=2.2kΩ
R139 "RC0603FR-102K2L" FP-MCR03-IPC_B 815,-1685 r180 top value=2.2kΩ
R140 "RC0603FR-102K2L" FP-MCR03-IPC_B -815,-1753 r180 top value=2.2kΩ
R141 "RC0603FR-102K2L" FP-MCR03-IPC_B 815,-1753 r0 top value=2.2kΩ
R142 "RT0603FRE07220RL" FP-MCR03-IPC_B -815,-1821 r0 top value=220Ω
R143 "RT0603FRE07220RL" FP-MCR03-IPC_B 815,-1821 r180 top value=220Ω
R144 "RC0603JR-07120RL" FP-MCR03-IPC_B -1360,-1912 r0 top value=120Ω
R145 "RC0603JR-07120RL" FP-MCR03-IPC_B 1360,-1980 r180 top value=120Ω
R146 "CRCW12100000Z0EAHP" RESC3125X70X40NL20T20 -415,-2013 r0 top value=0Ω
R147 "RCWE1210R910FKEA" RESC3125X70X40NL20T20 415,-2013 r180 top value=0.91Ω
R148 "RC0603JR-07120RL" FP-MCR03-IPC_B -1360,-2048 r0 top value=120Ω
R149 "RCWE1210R910FKEA" RESC3125X70X40NL20T20 -415,-2137 r0 top value=0.91Ω
R150 "CRCW12100000Z0EAHP" RESC3125X70X40NL20T20 415,-2137 r180 top value=0Ω
R151 "CRCW06030000Z0EB" FP-MCR03-IPC_B -585,-2170 r0 top value=0Ω
R152 "CRCW06030000Z0EB" FP-MCR03-IPC_B 585,-2170 r180 top value=0Ω
R153 "RC0603JR-07120RL" FP-MCR03-IPC_B 1360,-2252 r180 top value=120Ω
R154 "RC0603JR-07120RL" FP-MCR03-IPC_B -1360,-2320 r0 top value=120Ω
R155 "RC0603JR-07120RL" FP-MCR03-IPC_B 1360,-2388 r180 top value=120Ω
R156 "RC1206FR-07249RL" FP-MCR18-IPC_A -500,3585 r0 bottom value=249Ω
R157 "RC1206FR-07249RL" FP-MCR18-IPC_A -3100,3585 r180 bottom value=249Ω
R158 "RC1206FR-07249RL" FP-MCR18-IPC_A -500,3485 r180 bottom value=249Ω
R159 "RC1206FR-07249RL" FP-MCR18-IPC_A -3100,3485 r0 bottom value=249Ω
R160 "CRCW06030000Z0EB" FP-MCR03-IPC_B -4940,3325 r270 bottom value=0Ω
R161 "CRCW06030000Z0EB" FP-MCR03-IPC_B -5008,3325 r270 bottom value=0Ω
R162 "RC0603JR-07120RL" FP-MCR03-IPC_B 1370,2422 r180 bottom value=120Ω
R163 "RC0603JR-07120RL" FP-MCR03-IPC_B -1370,2422 r180 bottom value=120Ω
R164 "ERJ3EKF1002V" FP-MCR03-IPC_B 1370,2354 r180 bottom value=10kΩ
R165 "ERJ3EKF1002V" FP-MCR03-IPC_B -1370,2354 r0 bottom value=10kΩ
R166 "RC1210JR-07330RL" RESC3125X70X40NL20T20 655,2300 r90 bottom value=330Ω
R167 "RC0603FR-13330RL" FP-MCR03-IPC_B -3630,2330 r90 bottom value=330Ω
R168 "RC0603FR-13330RL" FP-MCR03-IPC_B -3698,2330 r270 bottom value=330Ω
R169 "RC0603FR-13330RL" FP-MCR03-IPC_B -3766,2330 r270 bottom value=330Ω
R170 "RC0603FR-13330RL" FP-MCR03-IPC_B -3834,2330 r90 bottom value=330Ω
R171 "CRCW06034K70FKTA" FP-MCR03-IPC_B -3902,2330 r270 bottom value=4.7kΩ
R172 "CRCW06034K70FKTA" FP-MCR03-IPC_B -3970,2330 r270 bottom value=4.7kΩ
R173 "CRCW06030000Z0EB" FP-MCR03-IPC_B 1370,2286 r0 bottom value=0Ω
R174 "RT0603BRD07107KL" FP-MCR03-IPC_B 500,2175 r180 bottom value=107kΩ
R175 "RT0603DRE0730KL" FP-MCR03-IPC_B -500,2175 r180 bottom value=30kΩ
R176 "RT0603FRE0749K9L" FP-MCR03-IPC_B -405,2141 r90 bottom value=49.9kΩ
R177 "RT0603BRD0716K2L" FP-MCR03-IPC_B 500,2107 r0 bottom value=16.2kΩ
R178 "ERJ3EKF1002V" FP-MCR03-IPC_B 337,2073 r270 bottom value=10kΩ
R179 "ERJ3EKF1002V" FP-MCR03-IPC_B -337,2073 r270 bottom value=10kΩ
R180 "RC1210JR-07330RL" RESC3125X70X40NL20T20 -655,1995 r270 bottom value=330Ω
R181 "RT0603BRD0716K2L" FP-MCR03-IPC_B -500,2039 r180 bottom value=16.2kΩ
R182 "RT0603FRE0749K9L" FP-MCR03-IPC_B 405,2005 r270 bottom value=49.9kΩ
R183 "RT0603DRE0730KL" FP-MCR03-IPC_B 500,1971 r0 bottom value=30kΩ
R184 "RT0603BRD07107KL" FP-MCR03-IPC_B -500,1971 r0 bottom value=107kΩ
R185 "CRCW06030000Z0EB" FP-MCR03-IPC_B -1370,1963 r180 bottom value=0Ω
R186 "RC0805FR-07499RL" FP-MCR10-IPC_A 1370,1885 r0 bottom value=499Ω
R187 "RC0805FR-07499RL" FP-MCR10-IPC_A -1370,1885 r180 bottom value=499Ω
R188 "ERJ3EKF1002V" FP-MCR03-IPC_B 1370,1772 r180 bottom value=10kΩ
R189 "ERJ3EKF1002V" FP-MCR03-IPC_B -1370,1772 r180 bottom value=10kΩ
R190 "ERJ3EKF1002V" FP-MCR03-IPC_B -1500,1772 r180 bottom value=10kΩ
R191 "RC0603JR-07120RL" FP-MCR03-IPC_B 1500,1704 r0 bottom value=120Ω
R192 "RC0603JR-07120RL" FP-MCR03-IPC_B -1370,1704 r0 bottom value=120Ω
R193 "ERJ3EKF1002V" FP-MCR03-IPC_B 1370,1636 r0 bottom value=10kΩ
R194 "RC0603JR-07120RL" FP-MCR03-IPC_B -1370,1636 r0 bottom value=120Ω
R195 "RC0603JR-07120RL" FP-MCR03-IPC_B 1370,1568 r180 bottom value=120Ω
R196 "RC0603JR-07120RL" FP-MCR03-IPC_B -1370,1568 r0 bottom value=120Ω
R197 "RC0603JR-07120RL" FP-MCR03-IPC_B 1370,1500 r180 bottom value=120Ω
R198 "RC0603JR-07120RL" FP-MCR03-IPC_B -1370,1500 r0 bottom value=120Ω
R199 "RC0603JR-07120RL" FP-MCR03-IPC_B 1370,1432 r180 bottom value=120Ω
R200 "RC0603JR-07120RL" FP-MCR03-IPC_B -1370,1432 r0 bottom value=120Ω
R201 "RC0603JR-07120RL" FP-MCR03-IPC_B 1370,1364 r180 bottom value=120Ω
R202 "ERJ3EKF1002V" FP-MCR03-IPC_B -1370,1364 r180 bottom value=10kΩ
R203 "RC0603JR-07120RL" FP-MCR03-IPC_B 1370,1296 r180 bottom value=120Ω
R204 "RC0603JR-07120RL" FP-MCR03-IPC_B -1500,1296 r180 bottom value=120Ω
R205 "ERJ3EKF1002V" FP-MCR03-IPC_B 1500,1228 r0 bottom value=10kΩ
R206 "ERJ3EKF1002V" FP-MCR03-IPC_B 1370,1228 r180 bottom value=10kΩ
R207 "ERJ3EKF1002V" FP-MCR03-IPC_B -1500,1228 r0 bottom value=10kΩ
R208 "RC0805FR-07499RL" FP-MCR10-IPC_A 1370,1115 r0 bottom value=499Ω
R209 "RC0805FR-07499RL" FP-MCR10-IPC_A -1370,1115 r180 bottom value=499Ω
R210 "RC1210JR-07330RL" RESC3125X70X40NL20T20 655,1005 r90 bottom value=330Ω
R211 "CRCW06030000Z0EB" FP-MCR03-IPC_B 1370,1037 r0 bottom value=0Ω
R212 "RT0603BRD07107KL" FP-MCR03-IPC_B 500,1029 r180 bottom value=107kΩ
R213 "RT0603DRE0730KL" FP-MCR03-IPC_B -500,1029 r180 bottom value=30kΩ
R214 "RT0603FRE0749K9L" FP-MCR03-IPC_B -405,995 r90 bottom value=49.9kΩ
R215 "RT0603BRD0716K2L" FP-MCR03-IPC_B 500,961 r0 bottom value=16.2kΩ
R216 "ERJ3EKF1002V" FP-MCR03-IPC_B 337,927 r90 bottom value=10kΩ
R217 "ERJ3EKF1002V" FP-MCR03-IPC_B -337,927 r90 bottom value=10kΩ
R218 "CRCW060320K0FKTA" FP-MCR03-IPC_B -3200,940 r180 bottom value=20kΩ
